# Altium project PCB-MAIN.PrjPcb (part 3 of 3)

## Sheet PCB-MAIN_07_BLE.SchDoc
size 594 x 420 mm
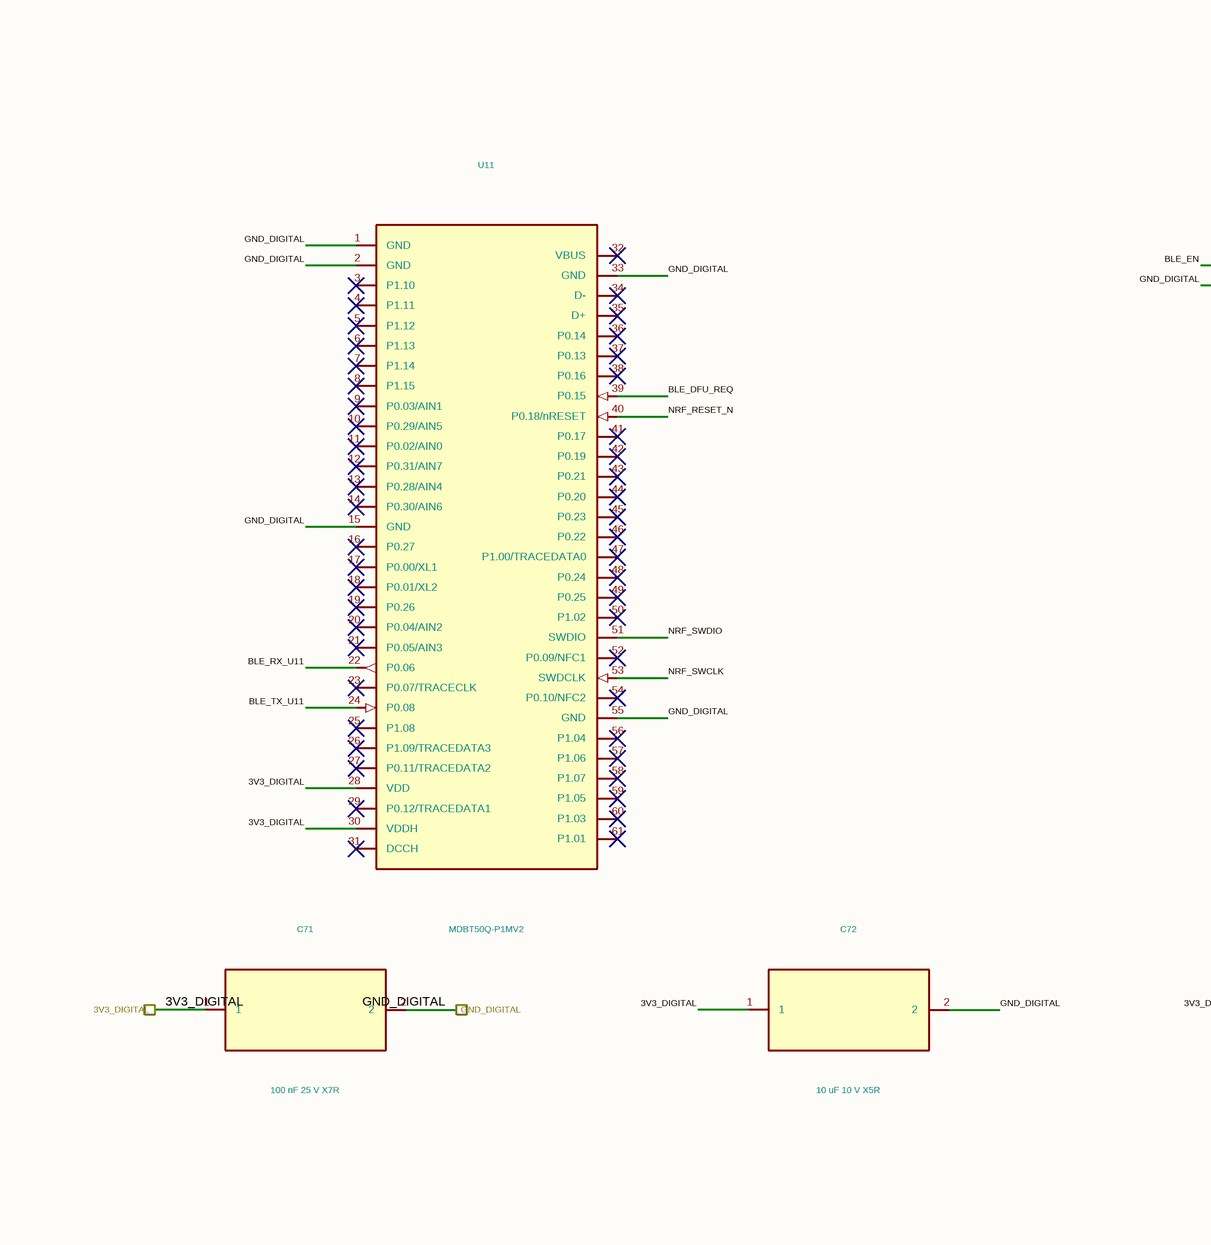
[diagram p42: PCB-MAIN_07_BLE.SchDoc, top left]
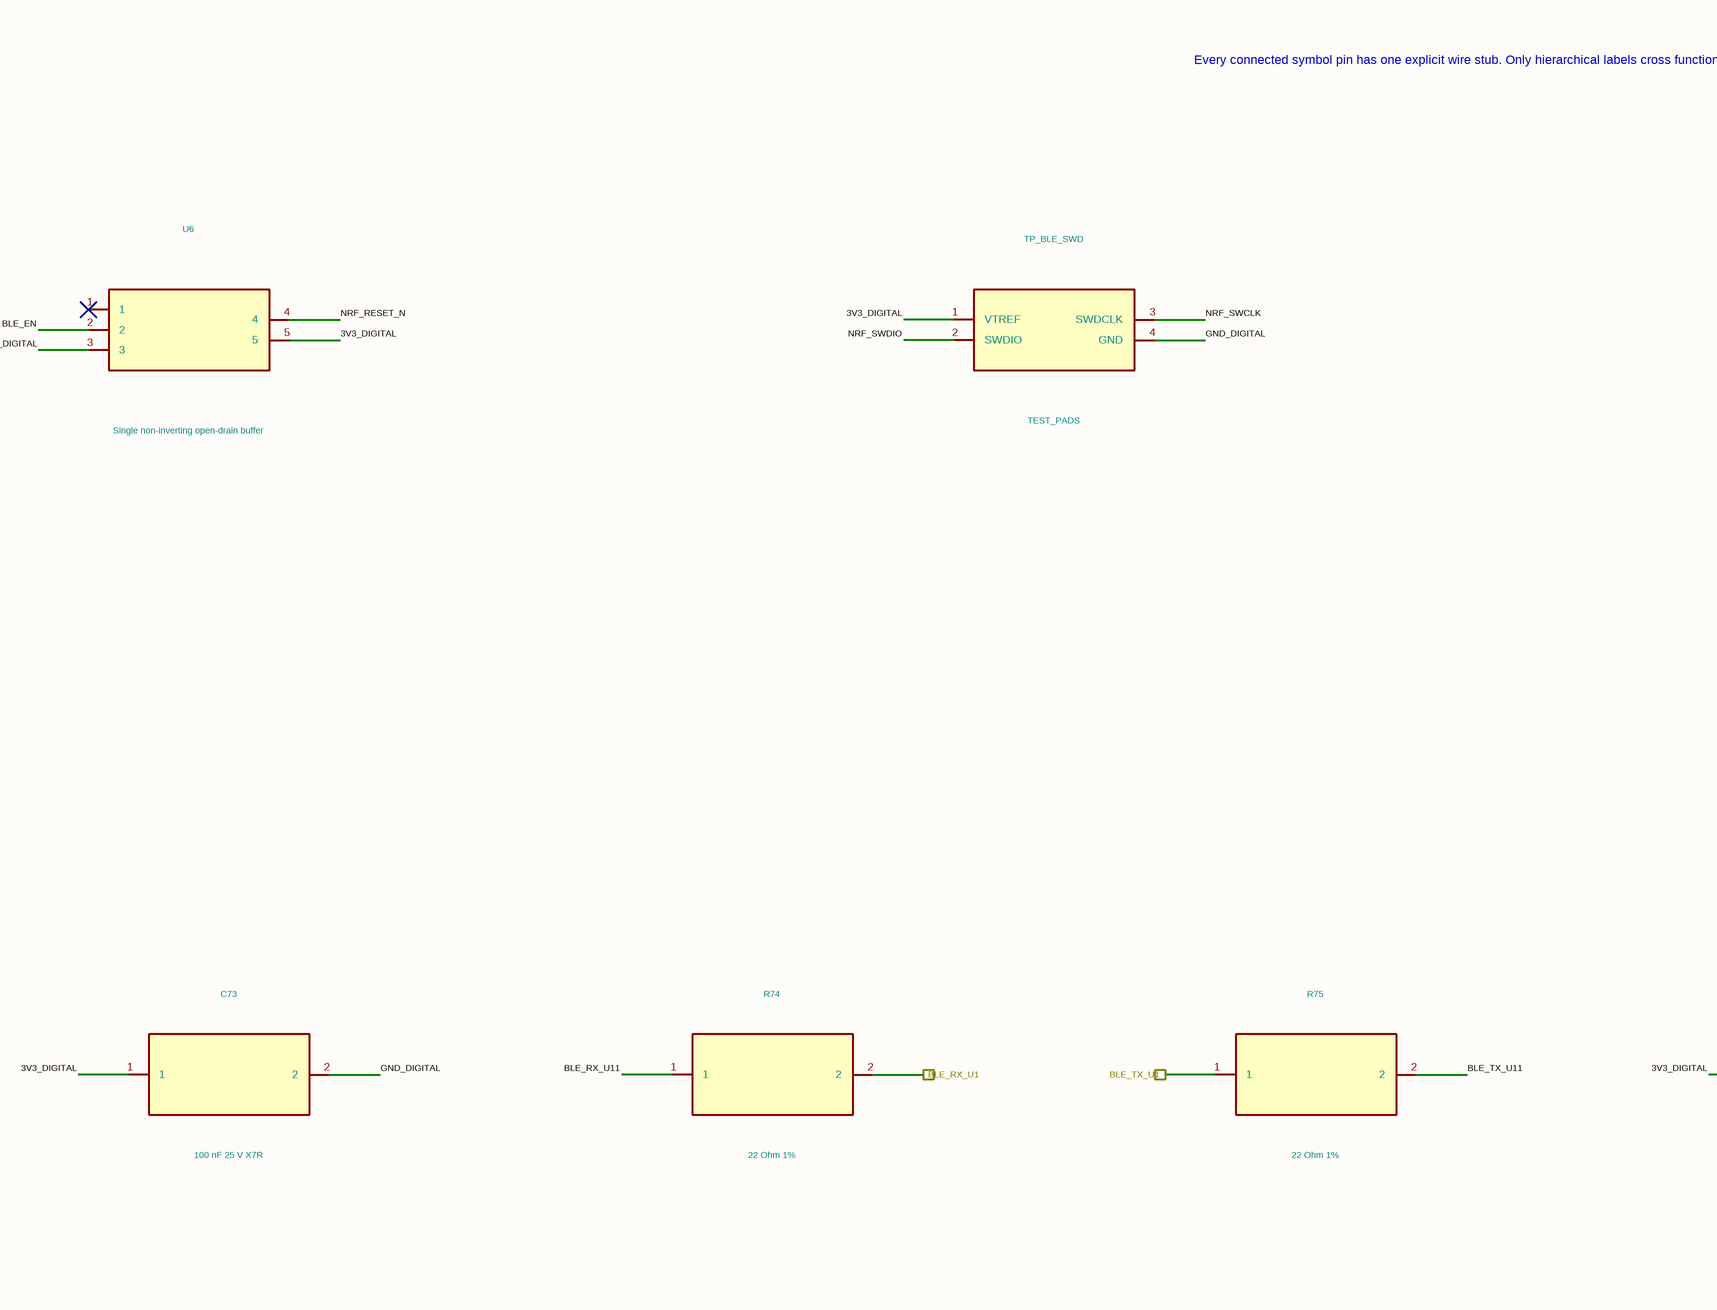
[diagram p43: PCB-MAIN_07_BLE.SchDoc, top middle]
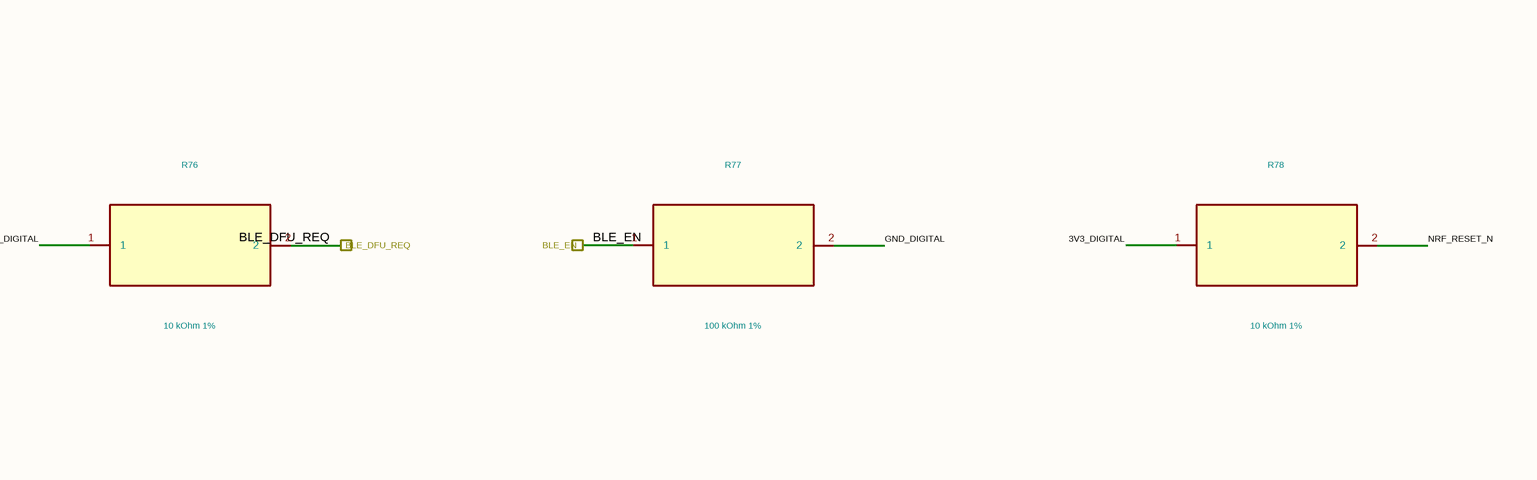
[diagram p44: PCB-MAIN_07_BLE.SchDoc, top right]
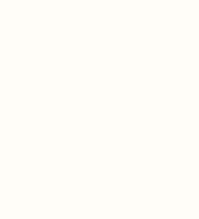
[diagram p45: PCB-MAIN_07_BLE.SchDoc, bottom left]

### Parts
C71  100 nF 25 V X7R  [C_0402_1005Metric]
C72  10 uF 10 V X5R  [C_0603_1608Metric]
C73  100 nF 25 V X7R  [C_0402_1005Metric]
R74  22 Ohm 1%  [R_0402_1005Metric]
R75  22 Ohm 1%  [R_0402_1005Metric]
R76  10 kOhm 1%  [R_0402_1005Metric]
R77  100 kOhm 1%  [R_0402_1005Metric]
R78  10 kOhm 1%  [R_0402_1005Metric]
TP_BLE_SWD  TEST_PADS
U6  Single non-inverting open-drain buffer
U11  MDBT50Q-P1MV2

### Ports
3V3_DIGITAL, BLE_DFU_REQ, BLE_EN, BLE_RX_U1, BLE_TX_U1, GND_DIGITAL

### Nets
3V3_DIGITAL: C71.1 C72.1 C73.1 R76.1 R78.1 TP_BLE_SWD.1(VTREF) U6.5 U11.28(VDD) U11.30(VDDH) ; port 3V3_DIGITAL
BLE_DFU_REQ: R76.2 U11.39(P0.15) ; port BLE_DFU_REQ
BLE_EN: R77.1 U6.2 ; port BLE_EN
BLE_RX_U1: R74.2 ; port BLE_RX_U1
BLE_RX_U11: R74.1 U11.22(P0.06)
BLE_TX_U1: R75.1 ; port BLE_TX_U1
BLE_TX_U11: R75.2 U11.24(P0.08)
GND_DIGITAL: C71.2 C72.2 C73.2 R77.2 TP_BLE_SWD.4(GND) U6.3 U11.1(GND) U11.2(GND) U11.15(GND) U11.33(GND) U11.55(GND) ; port GND_DIGITAL
NRF_RESET_N: R78.2 U6.4 U11.40(P0.18/nRESET)
NRF_SWCLK: TP_BLE_SWD.3(SWDCLK) U11.53(SWDCLK)
NRF_SWDIO: TP_BLE_SWD.2(SWDIO) U11.51(SWDIO)

Not connected (* = marked no-connect by the designer): U6 1*; U11 3(P1.10)* 4(P1.11)* 5(P1.12)* 6(P1.13)* 7(P1.14)* 8(P1.15)* 9(P0.03/AIN1)* 10(P0.29/AIN5)* 11(P0.02/AIN0)* 12(P0.31/AIN7)* 13(P0.28/AIN4)* 14(P0.30/AIN6)* 16(P0.27)* 17(P0.00/XL1)* 18(P0.01/XL2)* 19(P0.26)* 20(P0.04/AIN2)* 21(P0.05/AIN3)* 23(P0.07/TRACECLK)* 25(P1.08)* 26(P1.09/TRACEDATA3)* 27(P0.11/TRACEDATA2)* 29(P0.12/TRACEDATA1)* 31(DCCH)* 32(VBUS)* 34(D-)* 35(D+)* 36(P0.14)* 37(P0.13)* 38(P0.16)* 41(P0.17)* 42(P0.19)* 43(P0.21)* 44(P0.20)* 45(P0.23)* 46(P0.22)* 47(P1.00/TRACEDATA0)* 48(P0.24)* 49(P0.25)* 50(P1.02)* 52(P0.09/NFC1)* 54(P0.10/NFC2)* 56(P1.04)* 57(P1.06)* 58(P1.07)* 59(P1.05)* 60(P1.03)* 61(P1.01)*

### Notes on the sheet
- Every connected symbol pin has one explicit wire stub. Only hierarchical labels cross functional-sheet boundaries.

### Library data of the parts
C71 = C71_GRM155R71E104KE14D: Manufacturer: Murata; Population: FITTED; Authority: Raytac_MDBT50Q_Spec_Version_L
C72 = C72_GRM188R61A106KE69D: Manufacturer: Murata; Population: FITTED; Authority: Raytac_MDBT50Q_Spec_Version_L
C73 = C73_GRM155R71E104KE14D: Manufacturer: Murata; Population: FITTED; Authority: TI_SN74LVC1G07_datasheet
R74 = R74_ERJ-2RKF22R0X: Manufacturer: Panasonic; Population: FITTED; Authority: Raytac_MDBT50Q_Spec_Version_L
R75 = R75_ERJ-2RKF22R0X: Manufacturer: Panasonic; Population: FITTED; Authority: Raytac_MDBT50Q_Spec_Version_L
R76 = R76_ERJ-2RKF1002X: Manufacturer: Panasonic; Population: FITTED; Authority: Raytac_MDBT50Q_Spec_Version_L
R77 = R77_ERJ-2RKF1003X: Manufacturer: Panasonic; Population: FITTED; Authority: TI_SN74LVC1G07_datasheet
R78 = R78_ERJ-2RKF1002X: Manufacturer: Panasonic; Population: FITTED; Authority: TI_SN74LVC1G07_datasheet
TP_BLE_SWD = TP_BLE_SWD_TEST_PADS: Manufacturer: CONTROLLED_AUTHORITY; Population: FITTED; Authority: PCB_MAIN_BLE_PIN_AUTHORITY_REV_A.csv
U6 = U6_SN74LVC1G07DBVR: Manufacturer: Texas Instruments; Population: FITTED; Authority: TI_SN74LVC1G07_datasheet
U11 = U11_MDBT50Q-P1MV2: Manufacturer: Raytac; Population: FITTED; Authority: PCB_MAIN_BLE_PIN_AUTHORITY_REV_A.csv

## Sheet PCB-MAIN_08_STORAGE_SENSORS.SchDoc
size 594 x 420 mm
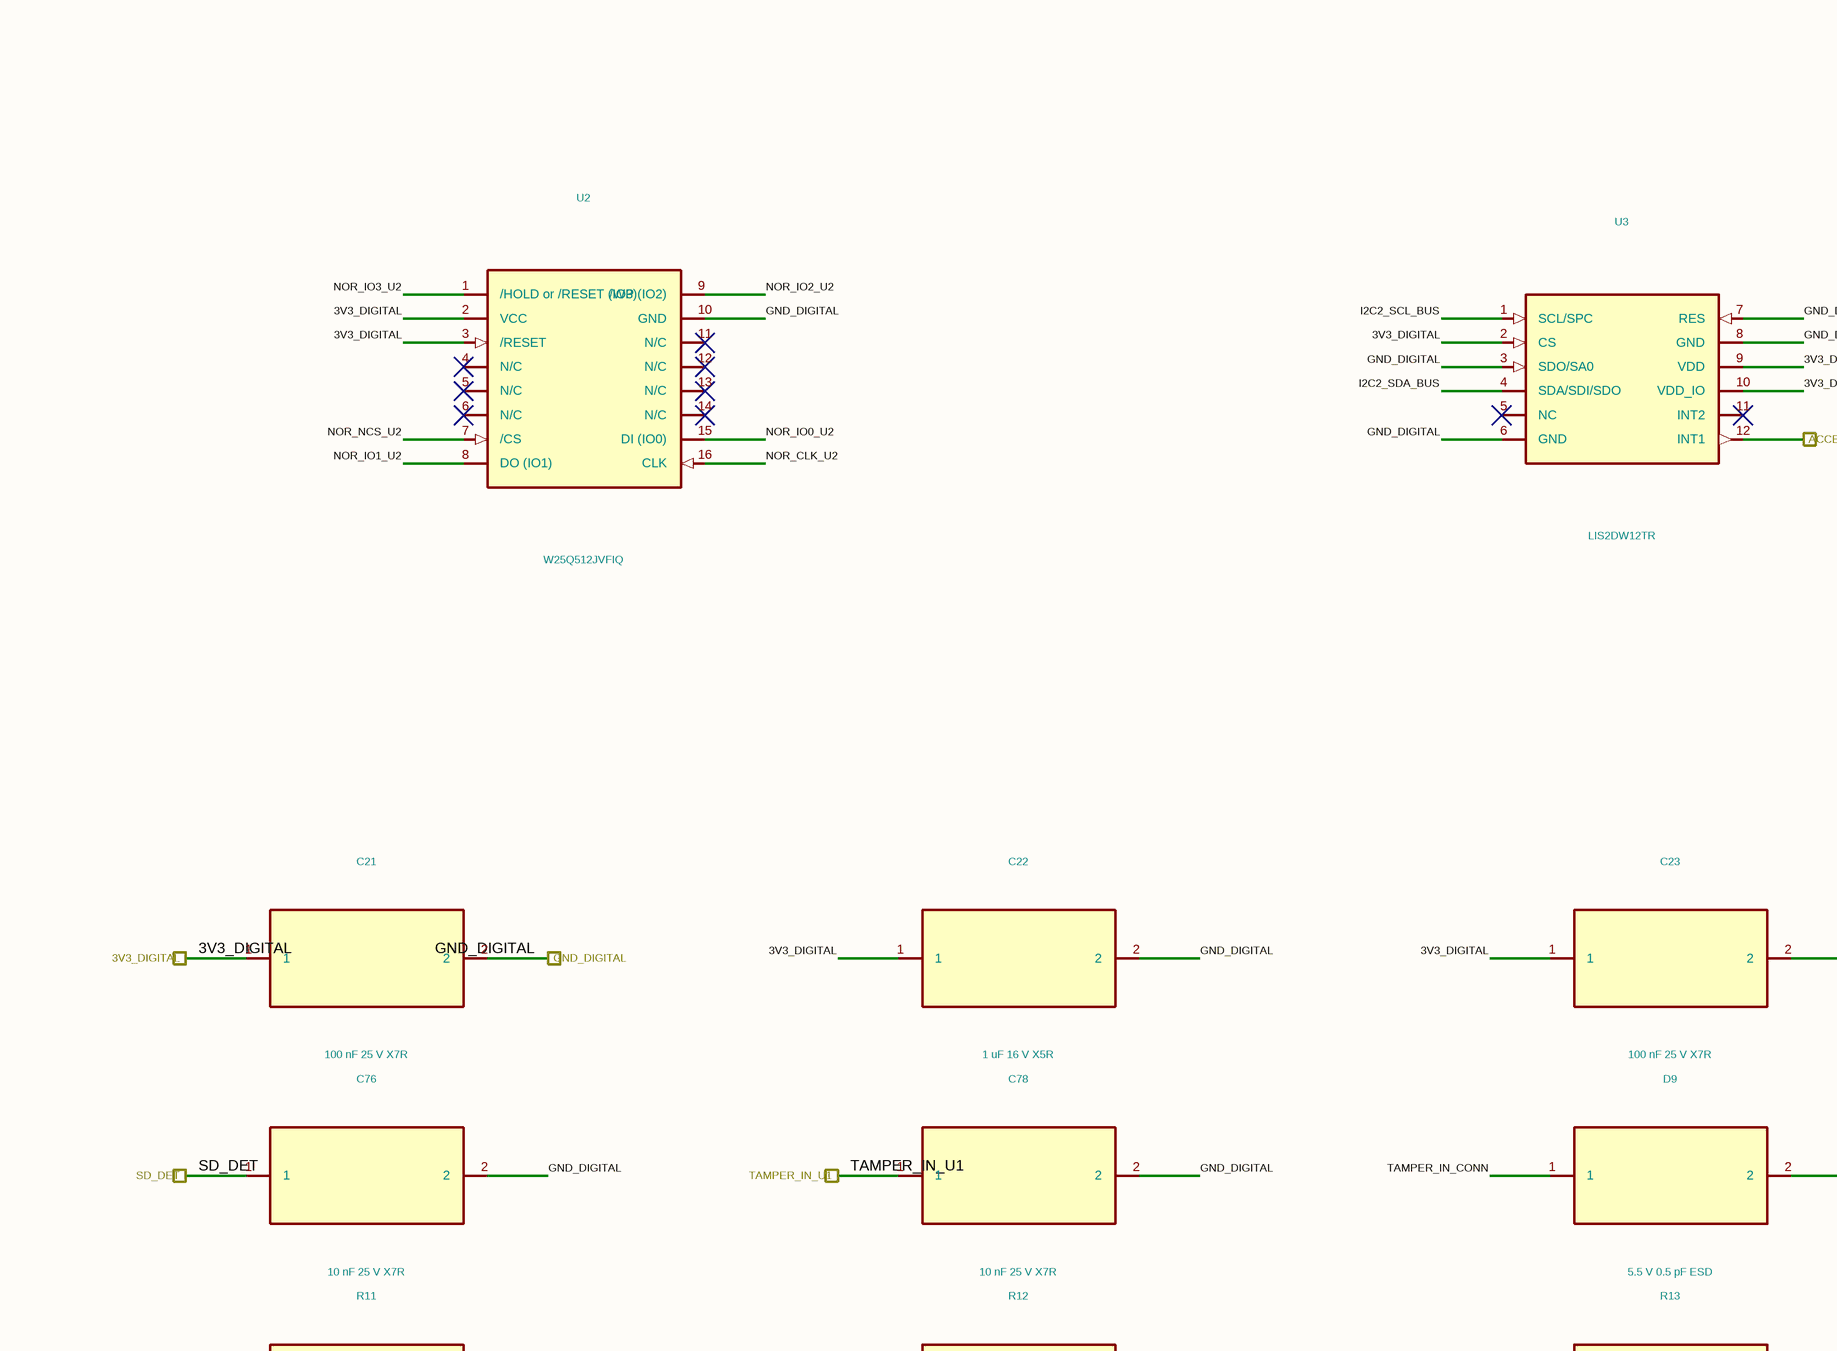
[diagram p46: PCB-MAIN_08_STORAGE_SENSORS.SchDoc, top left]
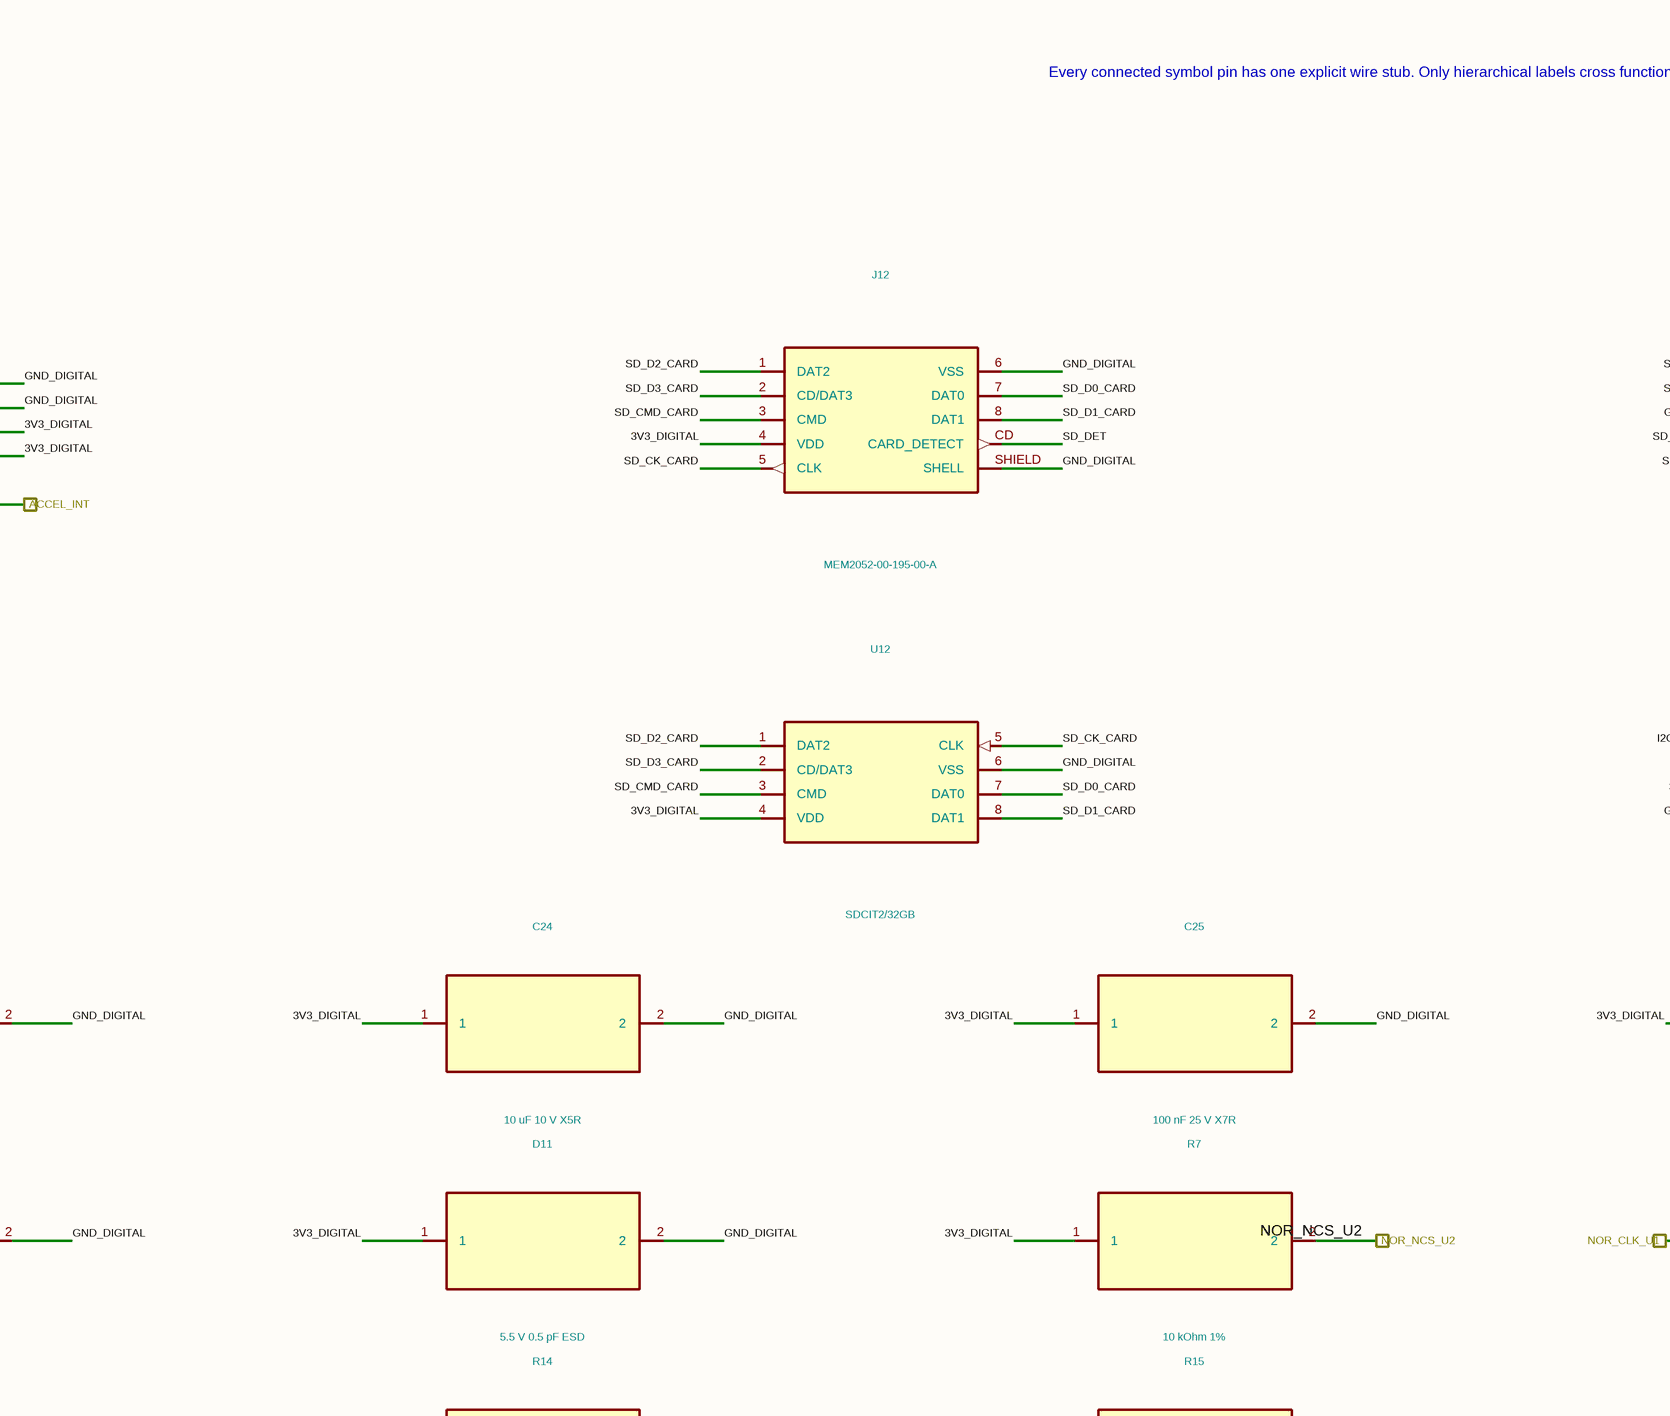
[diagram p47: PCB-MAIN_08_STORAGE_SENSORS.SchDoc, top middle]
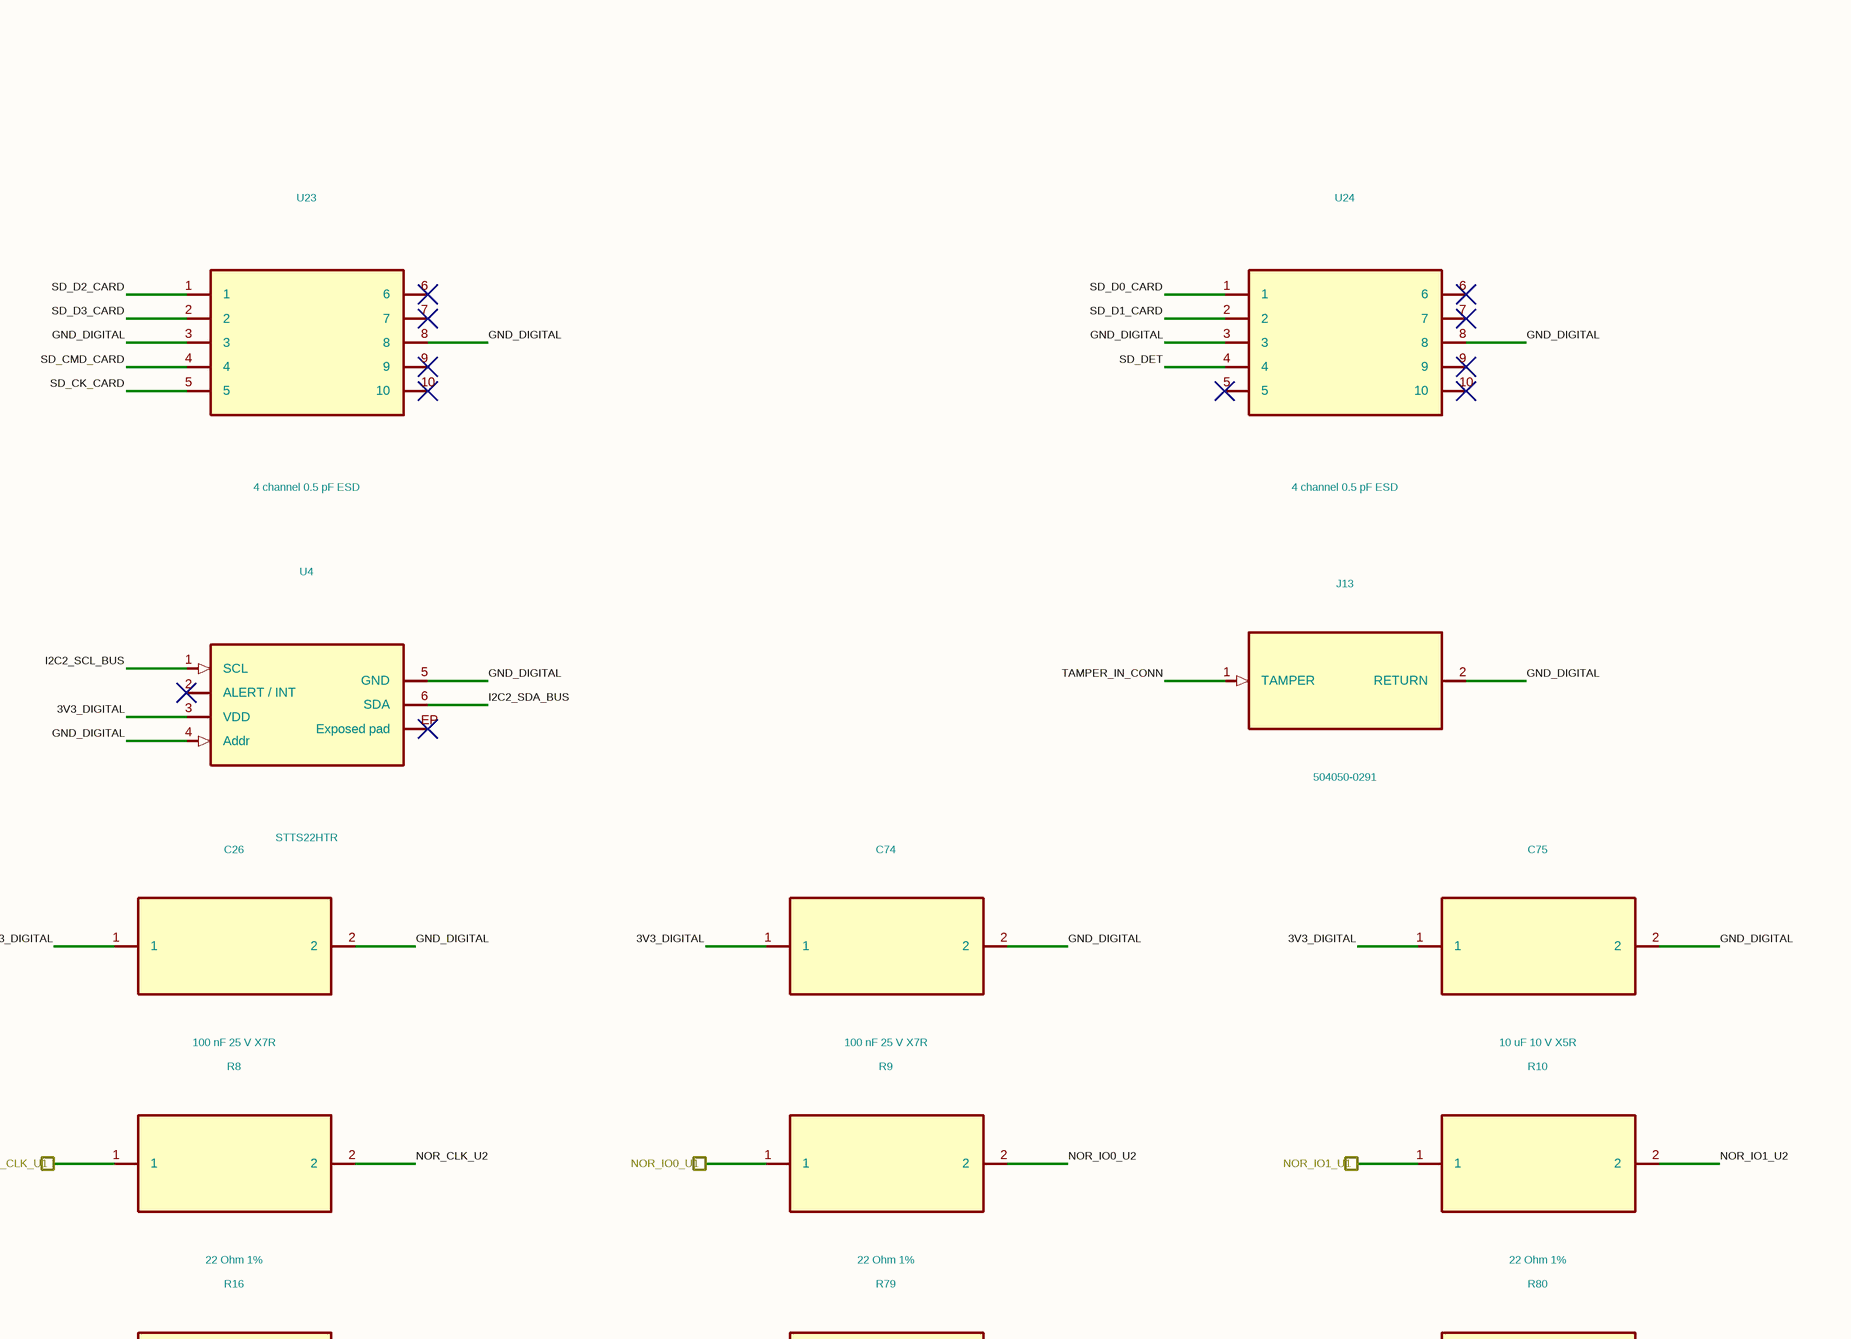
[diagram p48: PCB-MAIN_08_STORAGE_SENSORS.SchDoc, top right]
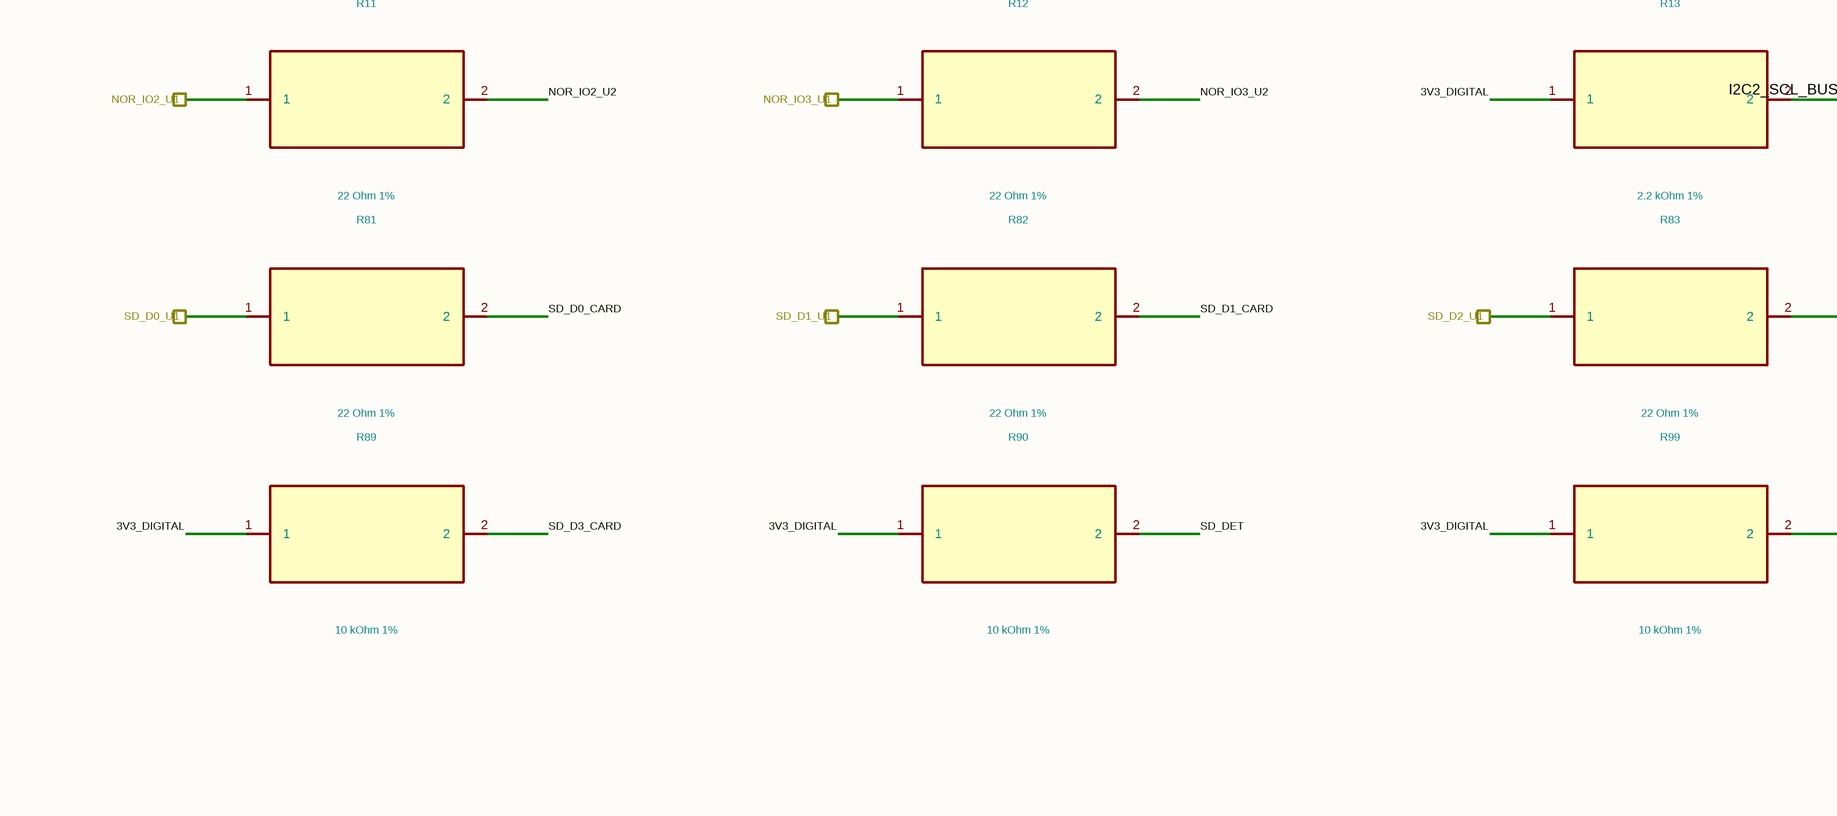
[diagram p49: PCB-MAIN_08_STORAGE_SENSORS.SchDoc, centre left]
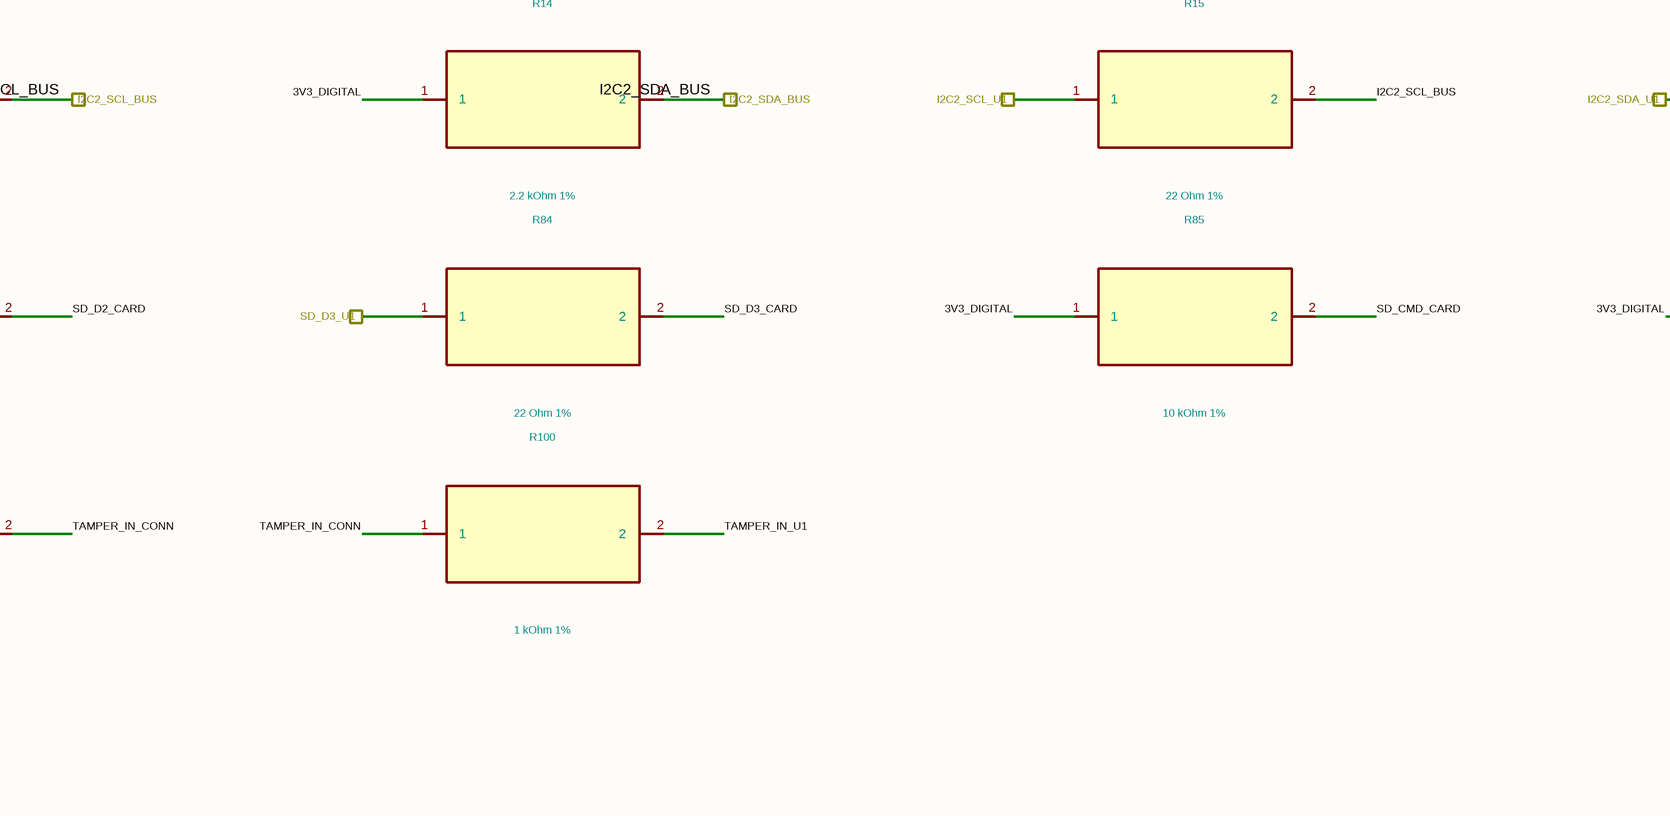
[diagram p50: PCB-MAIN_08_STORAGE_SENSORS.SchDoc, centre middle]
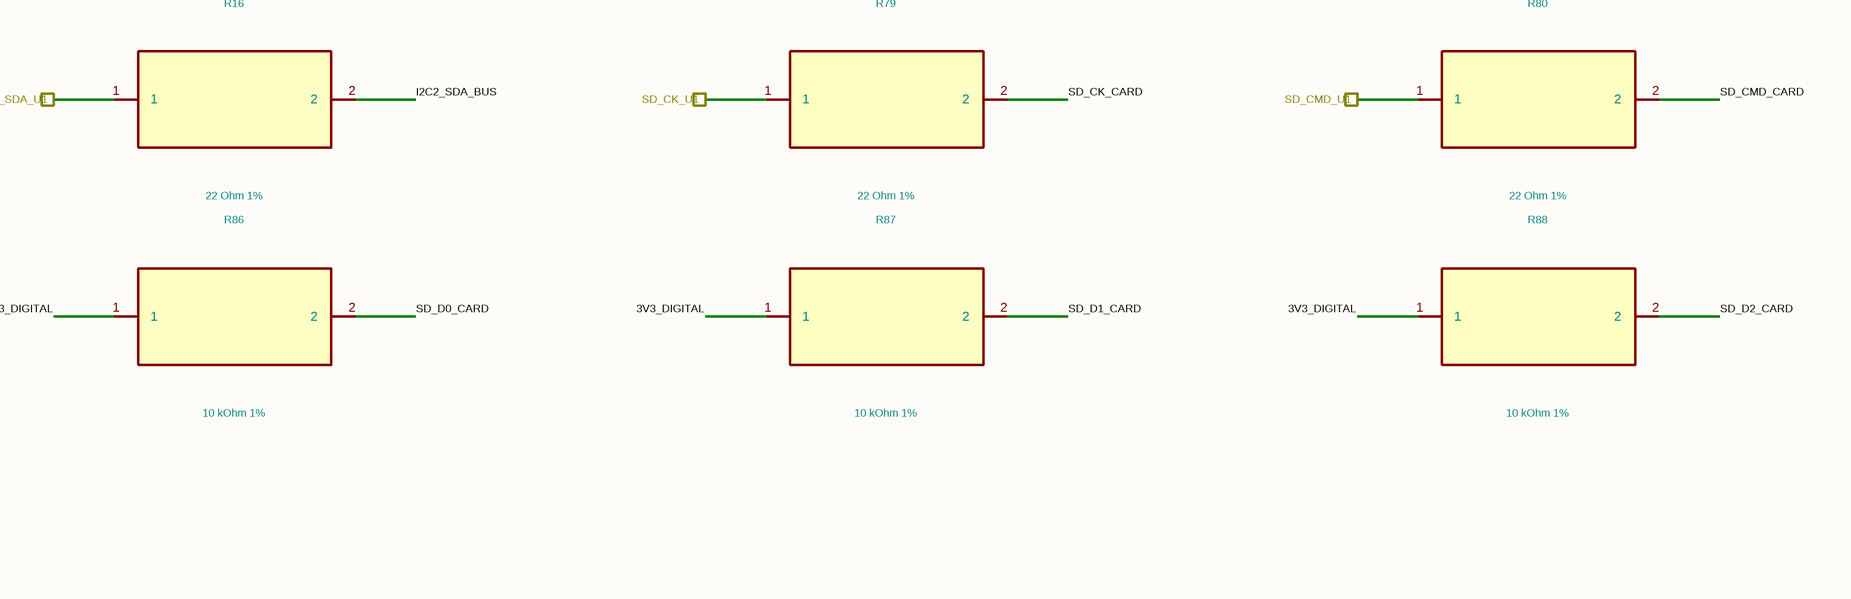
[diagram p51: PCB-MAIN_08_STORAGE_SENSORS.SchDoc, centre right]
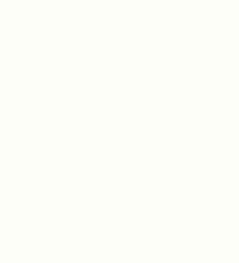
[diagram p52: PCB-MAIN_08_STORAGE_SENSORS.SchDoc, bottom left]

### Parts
C21  100 nF 25 V X7R  [C_0402_1005Metric]
C22  1 uF 16 V X5R  [C_0402_1005Metric]
C23  100 nF 25 V X7R  [C_0402_1005Metric]
C24  10 uF 10 V X5R  [C_0603_1608Metric]
C25  100 nF 25 V X7R  [C_0402_1005Metric]
C26  100 nF 25 V X7R  [C_0402_1005Metric]
C74  100 nF 25 V X7R  [C_0402_1005Metric]
C75  10 uF 10 V X5R  [C_0603_1608Metric]
C76  10 nF 25 V X7R  [C_0402_1005Metric]
C78  10 nF 25 V X7R  [C_0402_1005Metric]
D9  5.5 V 0.5 pF ESD
D11  5.5 V 0.5 pF ESD
J12  MEM2052-00-195-00-A
J13  504050-0291
R7  10 kOhm 1%  [R_0402_1005Metric]
R8  22 Ohm 1%  [R_0402_1005Metric]
R9  22 Ohm 1%  [R_0402_1005Metric]
R10  22 Ohm 1%  [R_0402_1005Metric]
R11  22 Ohm 1%  [R_0402_1005Metric]
R12  22 Ohm 1%  [R_0402_1005Metric]
R13  2.2 kOhm 1%  [R_0402_1005Metric]
R14  2.2 kOhm 1%  [R_0402_1005Metric]
R15  22 Ohm 1%  [R_0402_1005Metric]
R16  22 Ohm 1%  [R_0402_1005Metric]
R79  22 Ohm 1%  [R_0402_1005Metric]
R80  22 Ohm 1%  [R_0402_1005Metric]
R81  22 Ohm 1%  [R_0402_1005Metric]
R82  22 Ohm 1%  [R_0402_1005Metric]
R83  22 Ohm 1%  [R_0402_1005Metric]
R84  22 Ohm 1%  [R_0402_1005Metric]
R85  10 kOhm 1%  [R_0402_1005Metric]
R86  10 kOhm 1%  [R_0402_1005Metric]
R87  10 kOhm 1%  [R_0402_1005Metric]
R88  10 kOhm 1%  [R_0402_1005Metric]
R89  10 kOhm 1%  [R_0402_1005Metric]
R90  10 kOhm 1%  [R_0402_1005Metric]
R99  10 kOhm 1%  [R_0402_1005Metric]
R100  1 kOhm 1%  [R_0402_1005Metric]
U2  W25Q512JVFIQ
U3  LIS2DW12TR
U4  STTS22HTR
U12  SDCIT2/32GB
U23  4 channel 0.5 pF ESD
U24  4 channel 0.5 pF ESD

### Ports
3V3_DIGITAL, ACCEL_INT, GND_DIGITAL, I2C2_SCL_BUS, I2C2_SCL_U1, I2C2_SDA_BUS, I2C2_SDA_U1, NOR_CLK_U1, NOR_IO0_U1, NOR_IO1_U1, NOR_IO2_U1, NOR_IO3_U1, NOR_NCS_U2, SD_CK_U1, SD_CMD_U1, SD_D0_U1, SD_D1_U1, SD_D2_U1, SD_D3_U1, SD_DET, TAMPER_IN_U1

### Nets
3V3_DIGITAL: C21.1 C22.1 C23.1 C24.1 C25.1 C26.1 C74.1 C75.1 D11.1 J12.4(VDD) R7.1 R13.1 R14.1 R85.1 R86.1 R87.1 R88.1 R89.1 R90.1 R99.1 U2.2(VCC) U2.3(/RESET) U3.2(CS) U3.9(VDD) U3.10(VDD_IO) U4.3(VDD) U12.4(VDD) ; port 3V3_DIGITAL
ACCEL_INT: U3.12(INT1) ; port ACCEL_INT
GND_DIGITAL: C21.2 C22.2 C23.2 C24.2 C25.2 C26.2 C74.2 C75.2 C76.2 C78.2 D9.2 D11.2 J12.6(VSS) J12.SHIELD(SHELL) J13.2(RETURN) U2.10(GND) U3.3(SDO/SA0) U3.6(GND) U3.7(RES) U3.8(GND) U4.4(Addr) U4.5(GND) U12.6(VSS) U23.3 U23.8 U24.3 U24.8 ; port GND_DIGITAL
I2C2_SCL_BUS: R13.2 R15.2 U3.1(SCL/SPC) U4.1(SCL) ; port I2C2_SCL_BUS
I2C2_SCL_U1: R15.1 ; port I2C2_SCL_U1
I2C2_SDA_BUS: R14.2 R16.2 U3.4(SDA/SDI/SDO) U4.6(SDA) ; port I2C2_SDA_BUS
I2C2_SDA_U1: R16.1 ; port I2C2_SDA_U1
NOR_CLK_U1: R8.1 ; port NOR_CLK_U1
NOR_CLK_U2: R8.2 U2.16(CLK)
NOR_IO0_U1: R9.1 ; port NOR_IO0_U1
NOR_IO0_U2: R9.2 U2.15(DI_(IO0))
NOR_IO1_U1: R10.1 ; port NOR_IO1_U1
NOR_IO1_U2: R10.2 U2.8(DO_(IO1))
NOR_IO2_U1: R11.1 ; port NOR_IO2_U1
NOR_IO2_U2: R11.2 U2.9(/WP_(IO2))
NOR_IO3_U1: R12.1 ; port NOR_IO3_U1
NOR_IO3_U2: R12.2 U2.1(/HOLD_or_/RESET_(IO3))
NOR_NCS_U2: R7.2 U2.7(/CS) ; port NOR_NCS_U2
SD_CK_CARD: J12.5(CLK) R79.2 U12.5(CLK) U23.5
SD_CK_U1: R79.1 ; port SD_CK_U1
SD_CMD_CARD: J12.3(CMD) R80.2 R85.2 U12.3(CMD) U23.4
SD_CMD_U1: R80.1 ; port SD_CMD_U1
SD_D0_CARD: J12.7(DAT0) R81.2 R86.2 U12.7(DAT0) U24.1
SD_D0_U1: R81.1 ; port SD_D0_U1
SD_D1_CARD: J12.8(DAT1) R82.2 R87.2 U12.8(DAT1) U24.2
SD_D1_U1: R82.1 ; port SD_D1_U1
SD_D2_CARD: J12.1(DAT2) R83.2 R88.2 U12.1(DAT2) U23.1
SD_D2_U1: R83.1 ; port SD_D2_U1
SD_D3_CARD: J12.2(CD/DAT3) R84.2 R89.2 U12.2(CD/DAT3) U23.2
SD_D3_U1: R84.1 ; port SD_D3_U1
SD_DET: C76.1 J12.CD(CARD_DETECT) R90.2 U24.4 ; port SD_DET
TAMPER_IN_CONN: D9.1 J13.1(TAMPER) R99.2 R100.1
TAMPER_IN_U1: C78.1 R100.2 ; port TAMPER_IN_U1

Not connected (* = marked no-connect by the designer): U2 4(N/C)* 5(N/C)* 6(N/C)* 11(N/C)* 12(N/C)* 13(N/C)* 14(N/C)*; U3 5(NC)* 11(INT2)*; U4 2(ALERT_/_INT)* EP(Exposed_pad)*; U23 6* 7* 9* 10*; U24 5* 6* 7* 9* 10*

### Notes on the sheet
- Every connected symbol pin has one explicit wire stub. Only hierarchical labels cross functional-sheet boundaries.

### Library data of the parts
C21 = C21_GRM155R71E104KE14D: Manufacturer: Murata; Population: FITTED; Authority: Winbond_W25Q512JV_RevB
C22 = C22_GRM155R61C105KA12D: Manufacturer: Murata; Population: FITTED; Authority: Winbond_W25Q512JV_RevB
C23 = C23_GRM155R71E104KE14D: Manufacturer: Murata; Population: FITTED; Authority: ST_LIS2DW12_DS11811_Rev9
C24 = C24_GRM188R61A106KE69D: Manufacturer: Murata; Population: FITTED; Authority: ST_LIS2DW12_DS11811_Rev9
C25 = C25_GRM155R71E104KE14D: Manufacturer: Murata; Population: FITTED; Authority: ST_LIS2DW12_DS11811_Rev9
C26 = C26_GRM155R71E104KE14D: Manufacturer: Murata; Population: FITTED; Authority: ST_STTS22H_DS12606_Rev8
C74 = C74_GRM155R71E104KE14D: Manufacturer: Murata; Population: FITTED; Authority: SD_Association_microSD
C75 = C75_GRM188R61A106KE69D: Manufacturer: Murata; Population: FITTED; Authority: SD_Association_microSD
C76 = C76_GRM155R71E103KA01D: Manufacturer: Murata; Population: FITTED; Authority: GCT_MEM2052_official_product_data
C78 = C78_GRM155R71E103KA01D: Manufacturer: Murata; Population: FITTED; Authority: PROJECT_MAIN_AUTH_010
D9 = D9_TPD1E05U06DYAR: Manufacturer: Texas Instruments; Population: FITTED; Authority: TI_TPDxE05U06_RevO
D11 = D11_TPD1E05U06DYAR: Manufacturer: Texas Instruments; Population: FITTED; Authority: TI_TPDxE05U06_RevO
J12 = J12_MEM2052-00-195-00-A: Manufacturer: CONTROLLED_AUTHORITY; Population: FITTED; Authority: PCB_MAIN_CONNECTOR_FIXTURE_PIN_AUTHORITY_REV_A.csv
J13 = J13_504050-0291: Manufacturer: CONTROLLED_AUTHORITY; Population: FITTED; Authority: PCB_MAIN_CONNECTOR_FIXTURE_PIN_AUTHORITY_REV_A.csv
R7 = R7_ERJ-2RKF1002X: Manufacturer: Panasonic; Population: FITTED; Authority: Winbond_W25Q512JV_RevB
R8 = R8_ERJ-2RKF22R0X: Manufacturer: Panasonic; Population: FITTED; Authority: PROJECT_MAIN_AUTH_010
R9 = R9_ERJ-2RKF22R0X: Manufacturer: Panasonic; Population: FITTED; Authority: PROJECT_MAIN_AUTH_010
R10 = R10_ERJ-2RKF22R0X: Manufacturer: Panasonic; Population: FITTED; Authority: PROJECT_MAIN_AUTH_010
R11 = R11_ERJ-2RKF22R0X: Manufacturer: Panasonic; Population: FITTED; Authority: PROJECT_MAIN_AUTH_010
R12 = R12_ERJ-2RKF22R0X: Manufacturer: Panasonic; Population: FITTED; Authority: PROJECT_MAIN_AUTH_010
R13 = R13_ERJ-2RKF2201X: Manufacturer: Panasonic; Population: FITTED; Authority: I2C_UM10204
R14 = R14_ERJ-2RKF2201X: Manufacturer: Panasonic; Population: FITTED; Authority: I2C_UM10204
R15 = R15_ERJ-2RKF22R0X: Manufacturer: Panasonic; Population: FITTED; Authority: PROJECT_MAIN_AUTH_010
R16 = R16_ERJ-2RKF22R0X: Manufacturer: Panasonic; Population: FITTED; Authority: PROJECT_MAIN_AUTH_010
R79 = R79_ERJ-2RKF22R0X: Manufacturer: Panasonic; Population: FITTED; Authority: SD_Association_microSD
R80 = R80_ERJ-2RKF22R0X: Manufacturer: Panasonic; Population: FITTED; Authority: SD_Association_microSD
R81 = R81_ERJ-2RKF22R0X: Manufacturer: Panasonic; Population: FITTED; Authority: SD_Association_microSD
R82 = R82_ERJ-2RKF22R0X: Manufacturer: Panasonic; Population: FITTED; Authority: SD_Association_microSD
R83 = R83_ERJ-2RKF22R0X: Manufacturer: Panasonic; Population: FITTED; Authority: SD_Association_microSD
R84 = R84_ERJ-2RKF22R0X: Manufacturer: Panasonic; Population: FITTED; Authority: SD_Association_microSD
R85 = R85_ERJ-2RKF1002X: Manufacturer: Panasonic; Population: FITTED; Authority: SD_Association_microSD
R86 = R86_ERJ-2RKF1002X: Manufacturer: Panasonic; Population: FITTED; Authority: SD_Association_microSD
R87 = R87_ERJ-2RKF1002X: Manufacturer: Panasonic; Population: FITTED; Authority: SD_Association_microSD
R88 = R88_ERJ-2RKF1002X: Manufacturer: Panasonic; Population: FITTED; Authority: SD_Association_microSD
R89 = R89_ERJ-2RKF1002X: Manufacturer: Panasonic; Population: FITTED; Authority: SD_Association_microSD
R90 = R90_ERJ-2RKF1002X: Manufacturer: Panasonic; Population: FITTED; Authority: GCT_MEM2052_official_product_data
R99 = R99_ERJ-2RKF1002X: Manufacturer: Panasonic; Population: FITTED; Authority: PROJECT_MAIN_AUTH_010
R100 = R100_ERJ-2RKF1001X: Manufacturer: Panasonic; Population: FITTED; Authority: PROJECT_MAIN_AUTH_010
U2 = U2_W25Q512JVFIQ: Manufacturer: Winbond; Population: FITTED; Authority: PCB_MAIN_STORAGE_SENSOR_PIN_AUTHORITY_REV_A.csv
U3 = U3_LIS2DW12TR: Manufacturer: STMicroelectronics; Population: FITTED; Authority: PCB_MAIN_STORAGE_SENSOR_PIN_AUTHORITY_REV_A.csv
U4 = U4_STTS22HTR: Manufacturer: STMicroelectronics; Population: FITTED; Authority: PCB_MAIN_STORAGE_SENSOR_PIN_AUTHORITY_REV_A.csv
U12 = U12_SDCIT2_32GB: Manufacturer: Kingston; Population: FITTED; Authority: PCB_MAIN_CONNECTOR_FIXTURE_PIN_AUTHORITY_REV_A.csv
U23 = U23_TPD4E05U06DQAR: Manufacturer: Texas Instruments; Population: FITTED; Authority: TI_TPDxE05U06_RevO
U24 = U24_TPD4E05U06DQAR: Manufacturer: Texas Instruments; Population: FITTED; Authority: TI_TPDxE05U06_RevO

## Sheet PCB-MAIN_09_CONNECTORS_TEST.SchDoc
size 594 x 420 mm
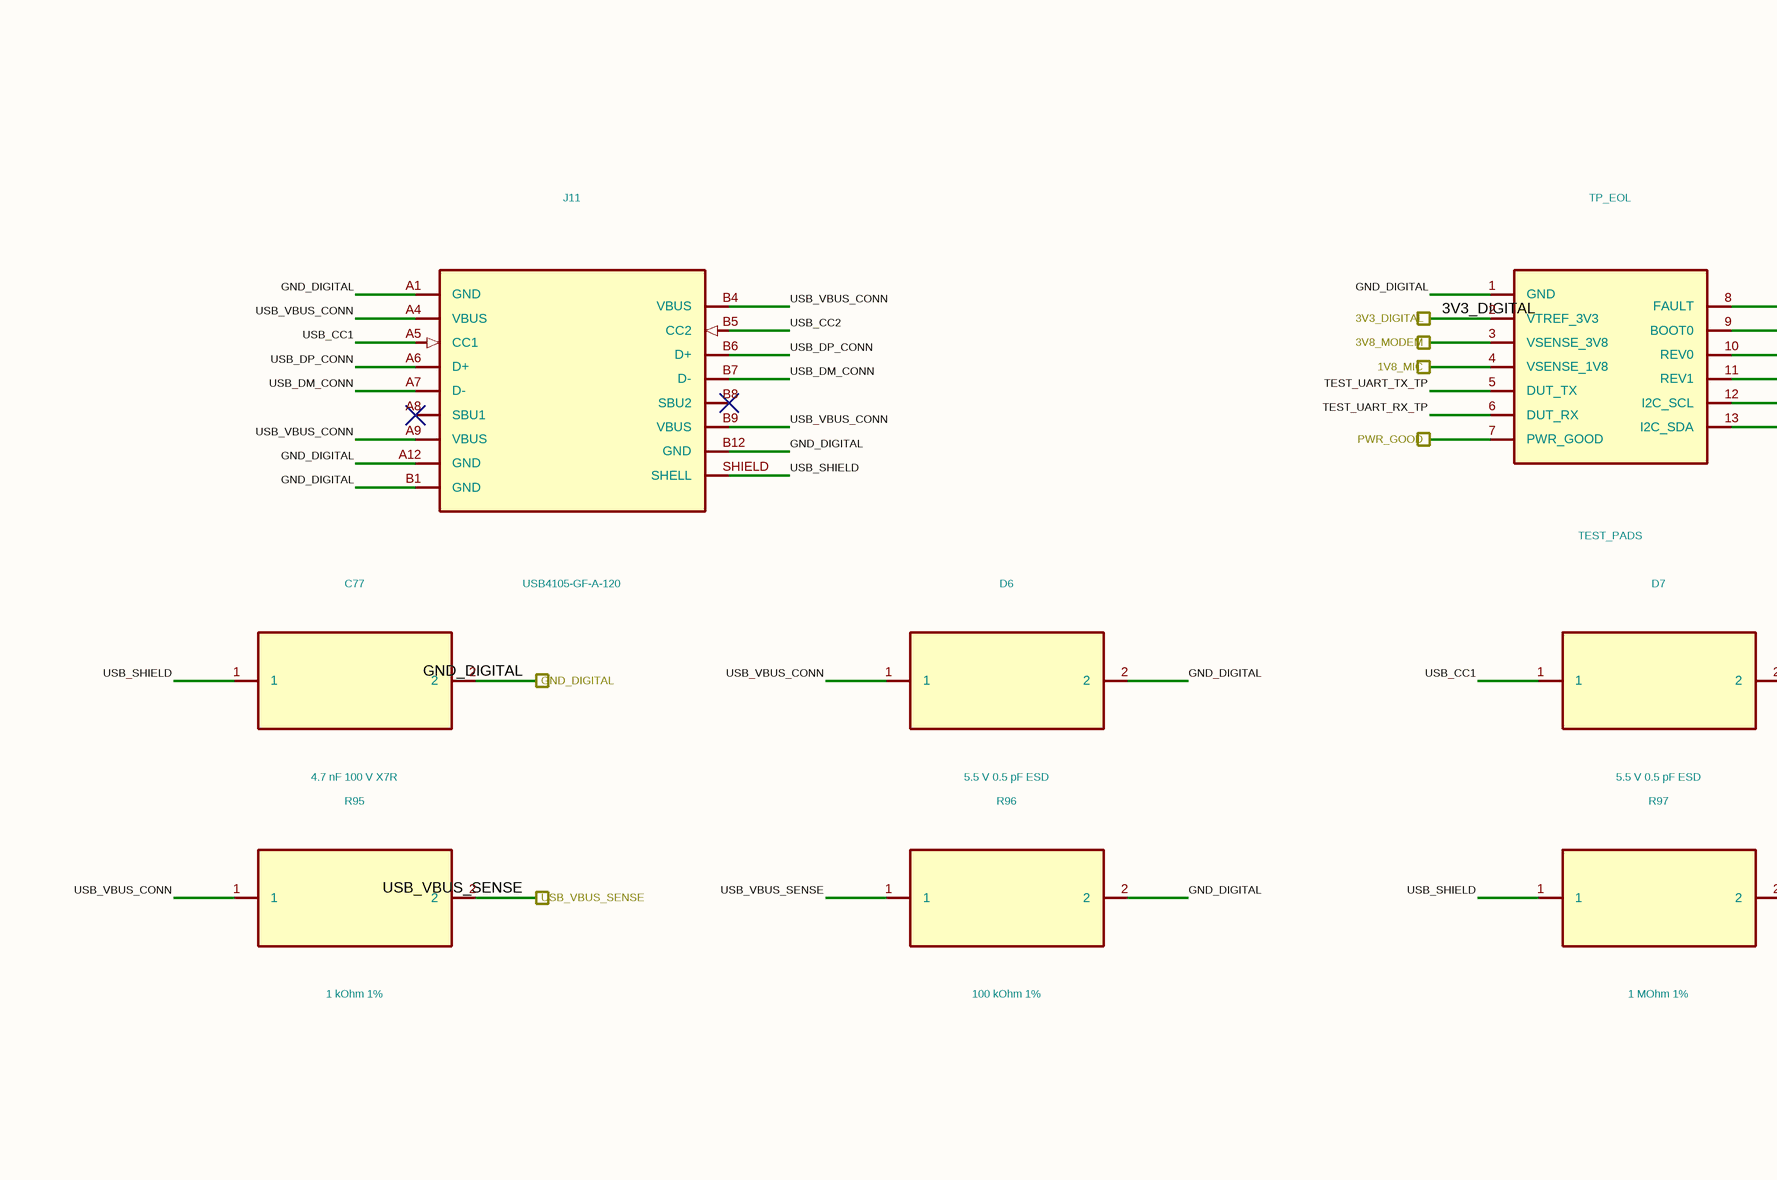
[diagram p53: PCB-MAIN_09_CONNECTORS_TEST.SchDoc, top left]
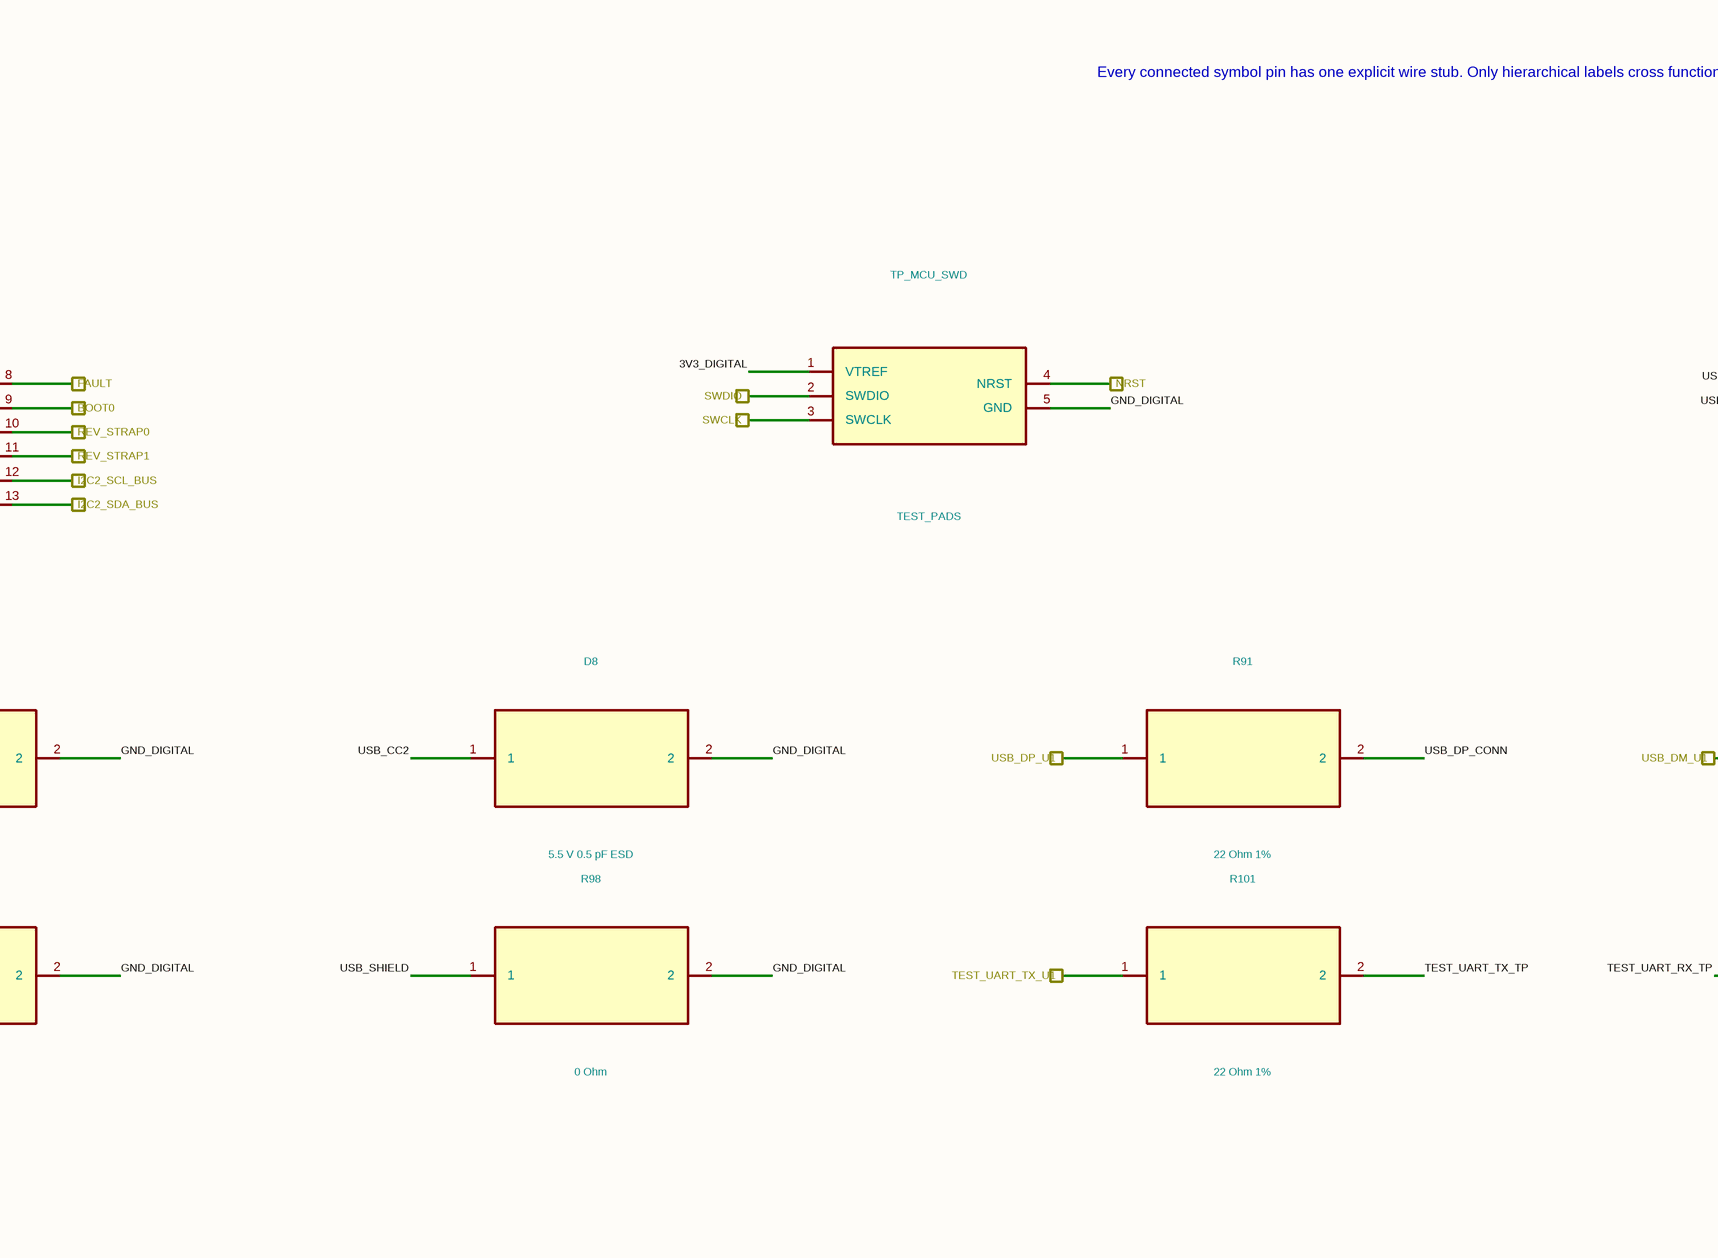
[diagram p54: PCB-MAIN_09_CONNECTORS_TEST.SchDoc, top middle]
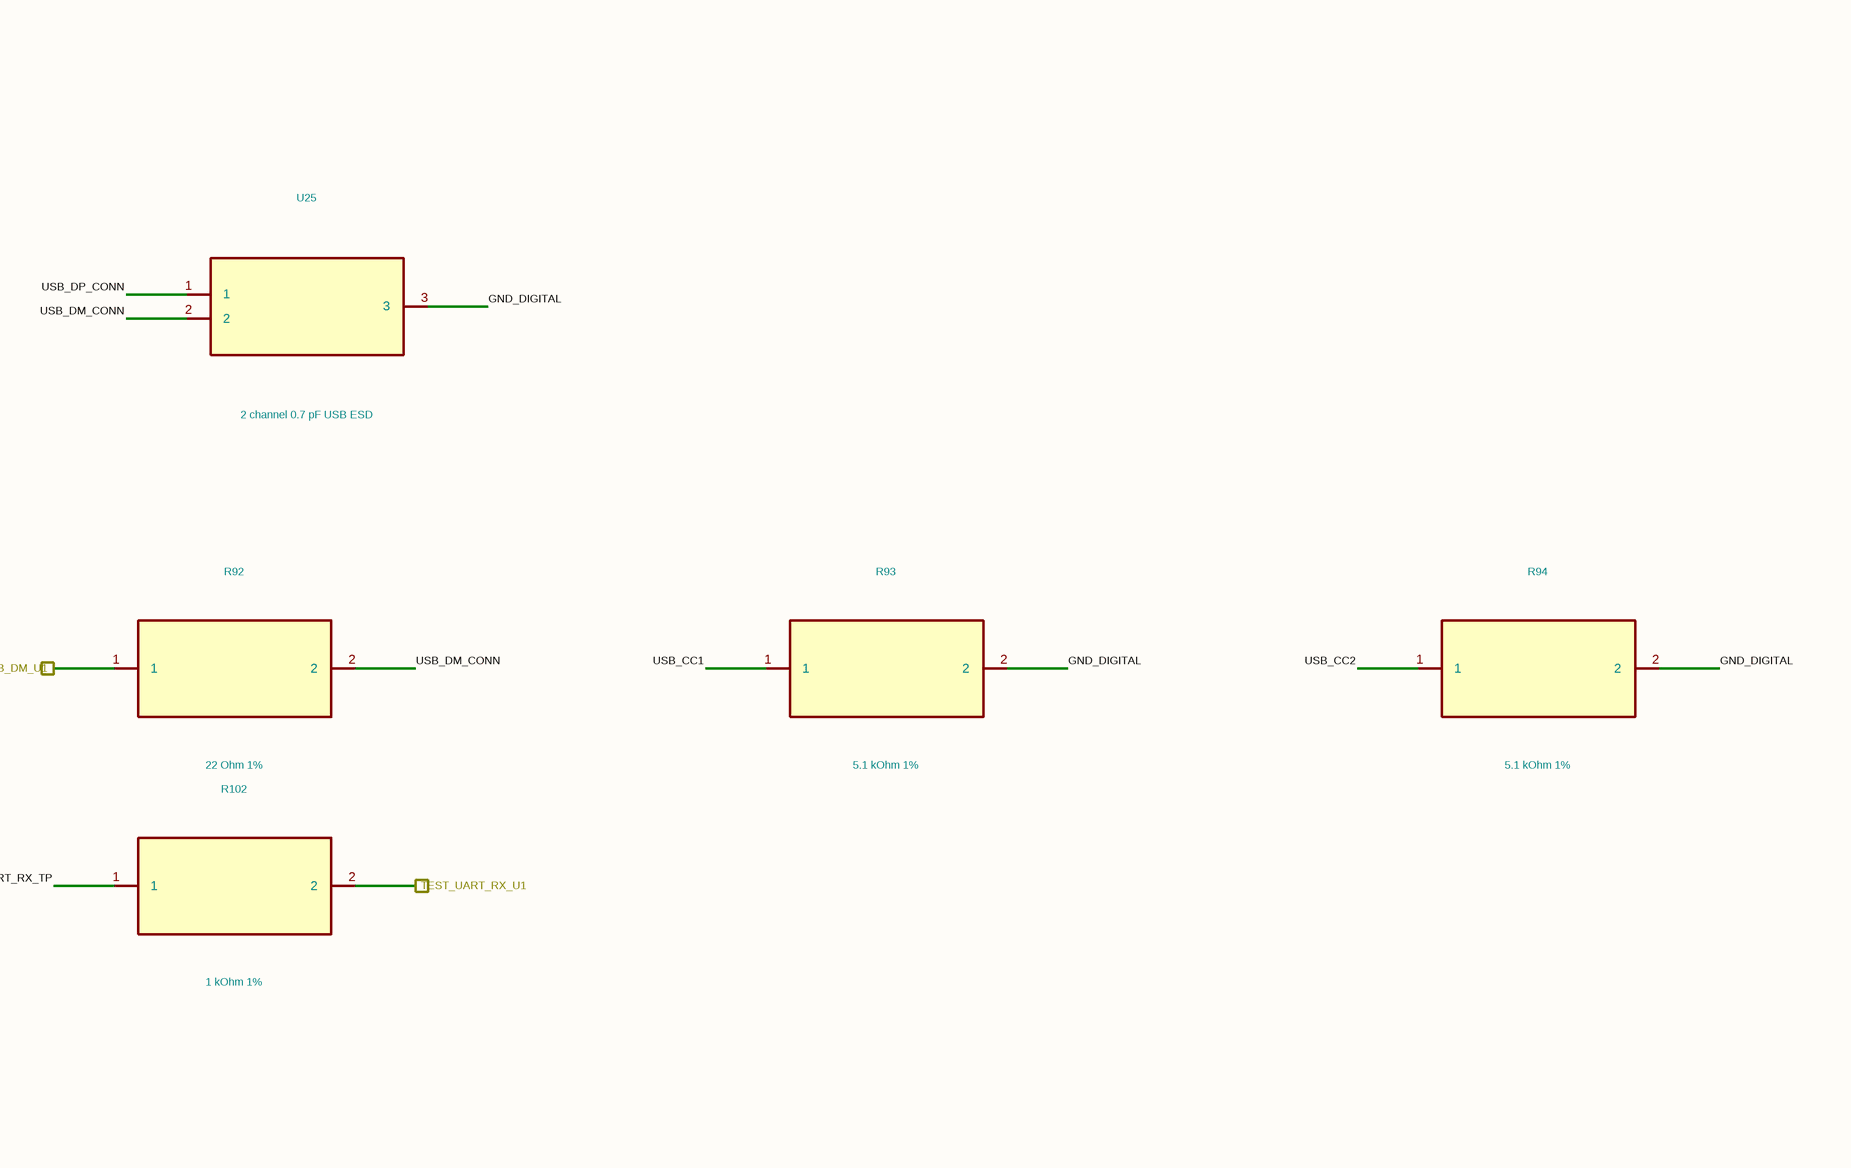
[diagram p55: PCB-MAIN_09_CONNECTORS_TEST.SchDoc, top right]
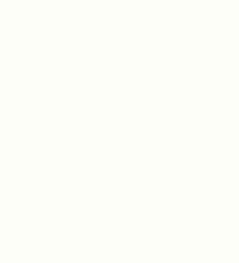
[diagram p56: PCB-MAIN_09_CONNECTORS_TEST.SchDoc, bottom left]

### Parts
C77  4.7 nF 100 V X7R  [C_0402_1005Metric]
D6  5.5 V 0.5 pF ESD
D7  5.5 V 0.5 pF ESD
D8  5.5 V 0.5 pF ESD
J11  USB4105-GF-A-120
R91  22 Ohm 1%  [R_0402_1005Metric]
R92  22 Ohm 1%  [R_0402_1005Metric]
R93  5.1 kOhm 1%  [R_0402_1005Metric]
R94  5.1 kOhm 1%  [R_0402_1005Metric]
R95  1 kOhm 1%  [R_0402_1005Metric]
R96  100 kOhm 1%  [R_0402_1005Metric]
R97  1 MOhm 1%  [R_0402_1005Metric]
R98  0 Ohm  [R_0402_1005Metric]
R101  22 Ohm 1%  [R_0402_1005Metric]
R102  1 kOhm 1%  [R_0402_1005Metric]
TP_EOL  TEST_PADS
TP_MCU_SWD  TEST_PADS
U25  2 channel 0.7 pF USB ESD

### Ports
1V8_MIC, 3V3_DIGITAL, 3V8_MODEM, BOOT0, FAULT, GND_DIGITAL, I2C2_SCL_BUS, I2C2_SDA_BUS, NRST, PWR_GOOD, REV_STRAP0, REV_STRAP1, SWCLK, SWDIO, TEST_UART_RX_U1, TEST_UART_TX_U1, USB_DM_U1, USB_DP_U1, USB_VBUS_SENSE

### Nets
1V8_MIC: TP_EOL.4(VSENSE_1V8) ; port 1V8_MIC
3V3_DIGITAL: TP_EOL.2(VTREF_3V3) TP_MCU_SWD.1(VTREF) ; port 3V3_DIGITAL
3V8_MODEM: TP_EOL.3(VSENSE_3V8) ; port 3V8_MODEM
BOOT0: TP_EOL.9(BOOT0) ; port BOOT0
FAULT: TP_EOL.8(FAULT) ; port FAULT
GND_DIGITAL: C77.2 D6.2 D7.2 D8.2 J11.A1(GND) J11.A12(GND) J11.B1(GND) J11.B12(GND) R93.2 R94.2 R96.2 R97.2 R98.2 TP_EOL.1(GND) TP_MCU_SWD.5(GND) U25.3 ; port GND_DIGITAL
I2C2_SCL_BUS: TP_EOL.12(I2C_SCL) ; port I2C2_SCL_BUS
I2C2_SDA_BUS: TP_EOL.13(I2C_SDA) ; port I2C2_SDA_BUS
NRST: TP_MCU_SWD.4(NRST) ; port NRST
PWR_GOOD: TP_EOL.7(PWR_GOOD) ; port PWR_GOOD
REV_STRAP0: TP_EOL.10(REV0) ; port REV_STRAP0
REV_STRAP1: TP_EOL.11(REV1) ; port REV_STRAP1
SWCLK: TP_MCU_SWD.3(SWCLK) ; port SWCLK
SWDIO: TP_MCU_SWD.2(SWDIO) ; port SWDIO
TEST_UART_RX_TP: R102.1 TP_EOL.6(DUT_RX)
TEST_UART_RX_U1: R102.2 ; port TEST_UART_RX_U1
TEST_UART_TX_TP: R101.2 TP_EOL.5(DUT_TX)
TEST_UART_TX_U1: R101.1 ; port TEST_UART_TX_U1
USB_CC1: D7.1 J11.A5(CC1) R93.1
USB_CC2: D8.1 J11.B5(CC2) R94.1
USB_DM_CONN: J11.A7(D-) J11.B7(D-) R92.2 U25.2
USB_DM_U1: R92.1 ; port USB_DM_U1
USB_DP_CONN: J11.A6(D+) J11.B6(D+) R91.2 U25.1
USB_DP_U1: R91.1 ; port USB_DP_U1
USB_SHIELD: C77.1 J11.SHIELD(SHELL) R97.1 R98.1
USB_VBUS_CONN: D6.1 J11.A4(VBUS) J11.A9(VBUS) J11.B4(VBUS) J11.B9(VBUS) R95.1
USB_VBUS_SENSE: R95.2 R96.1 ; port USB_VBUS_SENSE

Not connected (* = marked no-connect by the designer): J11 A8(SBU1)* B8(SBU2)*

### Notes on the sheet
- Every connected symbol pin has one explicit wire stub. Only hierarchical labels cross functional-sheet boundaries.

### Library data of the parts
C77 = C77_GRM155R72A472KA01D: Manufacturer: Murata; Population: FITTED; Authority: PROJECT_EMC_BASELINE
D6 = D6_TPD1E05U06DYAR: Manufacturer: Texas Instruments; Population: FITTED; Authority: TI_TPDxE05U06_RevO
D7 = D7_TPD1E05U06DYAR: Manufacturer: Texas Instruments; Population: FITTED; Authority: TI_TPDxE05U06_RevO
D8 = D8_TPD1E05U06DYAR: Manufacturer: Texas Instruments; Population: FITTED; Authority: TI_TPDxE05U06_RevO
J11 = J11_USB4105-GF-A-120: Manufacturer: CONTROLLED_AUTHORITY; Population: FITTED; Authority: PCB_MAIN_CONNECTOR_FIXTURE_PIN_AUTHORITY_REV_A.csv
R91 = R91_ERJ-2RKF22R0X: Manufacturer: Panasonic; Population: FITTED; Authority: ST_STM32U585_DS13086_Rev10
R92 = R92_ERJ-2RKF22R0X: Manufacturer: Panasonic; Population: FITTED; Authority: ST_STM32U585_DS13086_Rev10
R93 = R93_ERJ-2RKF5101X: Manufacturer: Panasonic; Population: FITTED; Authority: USB_Type-C_Release_2.5
R94 = R94_ERJ-2RKF5101X: Manufacturer: Panasonic; Population: FITTED; Authority: USB_Type-C_Release_2.5
R95 = R95_ERJ-2RKF1001X: Manufacturer: Panasonic; Population: FITTED; Authority: ST_STM32U585_DS13086_Rev10
R96 = R96_ERJ-2RKF1003X: Manufacturer: Panasonic; Population: FITTED; Authority: PROJECT_MAIN_AUTH_010
R97 = R97_ERJ-2RKF1004X: Manufacturer: Panasonic; Population: FITTED; Authority: PROJECT_EMC_BASELINE
R98 = R98_ERJ-2GE0R00X: Manufacturer: Panasonic; Population: DNP; Authority: PROJECT_EMC_BASELINE
R101 = R101_ERJ-2RKF22R0X: Manufacturer: Panasonic; Population: FITTED; Authority: PROJECT_EOL_DFT
R102 = R102_ERJ-2RKF1001X: Manufacturer: Panasonic; Population: FITTED; Authority: PROJECT_EOL_DFT
TP_EOL = TP_EOL_TEST_PADS: Manufacturer: CONTROLLED_AUTHORITY; Population: FITTED; Authority: PCB_MAIN_CONNECTOR_FIXTURE_PIN_AUTHORITY_REV_A.csv
TP_MCU_SWD = TP_MCU_SWD_TEST_PADS: Manufacturer: CONTROLLED_AUTHORITY; Population: FITTED; Authority: PCB_MAIN_CONNECTOR_FIXTURE_PIN_AUTHORITY_REV_A.csv
U25 = U25_TPD2EUSB30DRTR: Manufacturer: Texas Instruments; Population: FITTED; Authority: TI_TPD2EUSB30_datasheet

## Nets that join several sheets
1V8_MIC: PCB-MAIN_01_POWER (C20.1 J_PWR.5), PCB-MAIN_03_AUDIO (12 pins), PCB-MAIN_09_CONNECTORS_TEST (TP_EOL.4)
3V3_DIGITAL: PCB-MAIN_01_POWER (C19.1 J_PWR.3), PCB-MAIN_02_MCU (25 pins), PCB-MAIN_03_AUDIO (6 pins), PCB-MAIN_04_GNSS (5 pins), PCB-MAIN_05_CELLULAR (12 pins), PCB-MAIN_06_LORA (5 pins), PCB-MAIN_07_BLE (9 pins), PCB-MAIN_08_STORAGE_SENSORS (27 pins), PCB-MAIN_09_CONNECTORS_TEST (TP_EOL.2 TP_MCU_SWD.1)
3V8_MODEM: PCB-MAIN_01_POWER (J_PWR.1), PCB-MAIN_05_CELLULAR (FB1.1 R42.1), PCB-MAIN_09_CONNECTORS_TEST (TP_EOL.3)
AAD_CFG: PCB-MAIN_02_MCU (U1.77), PCB-MAIN_03_AUDIO (U7.16)
ACCEL_INT: PCB-MAIN_02_MCU (U1.63), PCB-MAIN_08_STORAGE_SENSORS (U3.12)
BLE_DFU_REQ: PCB-MAIN_02_MCU (U1.34), PCB-MAIN_07_BLE (R76.2 U11.39)
BLE_EN: PCB-MAIN_02_MCU (U1.5), PCB-MAIN_07_BLE (R77.1 U6.2)
BLE_RX_U1: PCB-MAIN_02_MCU (U1.45), PCB-MAIN_07_BLE (R74.2)
BLE_TX_U1: PCB-MAIN_02_MCU (U1.44), PCB-MAIN_07_BLE (R75.1)
BOOT0: PCB-MAIN_02_MCU (R2.1 U1.94), PCB-MAIN_09_CONNECTORS_TEST (TP_EOL.9)
CELL_DTR_U16: PCB-MAIN_02_MCU (U1.61), PCB-MAIN_05_CELLULAR (R29.1 U16.16)
CELL_PWRKEY_CMD: PCB-MAIN_02_MCU (U1.58), PCB-MAIN_05_CELLULAR (R24.1)
CELL_RESET_N_CMD: PCB-MAIN_02_MCU (U1.59), PCB-MAIN_05_CELLULAR (R26.1)
CELL_RI_U16: PCB-MAIN_02_MCU (U1.62), PCB-MAIN_05_CELLULAR (R33.2 U16.19)
CELL_RX_U16: PCB-MAIN_02_MCU (U1.93), PCB-MAIN_05_CELLULAR (R32.2 U16.21)
CELL_STATUS_U16: PCB-MAIN_02_MCU (U1.60), PCB-MAIN_05_CELLULAR (R34.1 U16.20)
CELL_TX_U16: PCB-MAIN_02_MCU (U1.92), PCB-MAIN_05_CELLULAR (R28.2 U16.17)
EN_AUX: PCB-MAIN_01_POWER (J_PWR.10), PCB-MAIN_02_MCU (U1.86)
EN_MODEM: PCB-MAIN_01_POWER (J_PWR.9), PCB-MAIN_02_MCU (U1.85)
FAULT: PCB-MAIN_01_POWER (J_PWR.8 R103.1), PCB-MAIN_09_CONNECTORS_TEST (TP_EOL.8)
GND_DIGITAL: PCB-MAIN_01_POWER (C19.2 J_PWR.4), PCB-MAIN_02_MCU (30 pins), PCB-MAIN_03_AUDIO (13 pins), PCB-MAIN_04_GNSS (17 pins), PCB-MAIN_06_LORA (21 pins), PCB-MAIN_07_BLE (11 pins), PCB-MAIN_08_STORAGE_SENSORS (27 pins), PCB-MAIN_09_CONNECTORS_TEST (16 pins)
GND_MIC: PCB-MAIN_01_POWER (C20.2 J_PWR.6), PCB-MAIN_03_AUDIO (20 pins)
GND_MODEM: PCB-MAIN_01_POWER (J_PWR.2), PCB-MAIN_05_CELLULAR (92 pins)
GNSS_PPS_U1: PCB-MAIN_02_MCU (U1.22), PCB-MAIN_04_GNSS (R58.2)
GNSS_RX_U1: PCB-MAIN_02_MCU (U1.25), PCB-MAIN_04_GNSS (R56.2)
GNSS_TX_U1: PCB-MAIN_02_MCU (U1.24), PCB-MAIN_04_GNSS (R57.1)
I2C2_SCL_BUS: PCB-MAIN_01_POWER (J_PWR.11), PCB-MAIN_08_STORAGE_SENSORS (R13.2 R15.2 U3.1 U4.1), PCB-MAIN_09_CONNECTORS_TEST (TP_EOL.12)
I2C2_SCL_U1: PCB-MAIN_02_MCU (U1.52), PCB-MAIN_08_STORAGE_SENSORS (R15.1)
I2C2_SDA_BUS: PCB-MAIN_01_POWER (J_PWR.12), PCB-MAIN_08_STORAGE_SENSORS (R14.2 R16.2 U3.4 U4.6), PCB-MAIN_09_CONNECTORS_TEST (TP_EOL.13)
I2C2_SDA_U1: PCB-MAIN_02_MCU (U1.53), PCB-MAIN_08_STORAGE_SENSORS (R16.1)
LORA_BUSY: PCB-MAIN_02_MCU (U1.56), PCB-MAIN_06_LORA (R66.1 U10.14)
LORA_DIO1: PCB-MAIN_02_MCU (U1.17), PCB-MAIN_06_LORA (R65.1 U10.13)
LORA_MISO_U1: PCB-MAIN_02_MCU (U1.30), PCB-MAIN_06_LORA (R72.2)
LORA_MOSI_U1: PCB-MAIN_02_MCU (U1.31), PCB-MAIN_06_LORA (R71.1)
LORA_NSS_U1: PCB-MAIN_02_MCU (U1.28), PCB-MAIN_06_LORA (R69.1)
LORA_RESET_N: PCB-MAIN_02_MCU (U1.57), PCB-MAIN_06_LORA (C68.1 R67.2 U10.15)
LORA_RXEN: PCB-MAIN_02_MCU (U1.55), PCB-MAIN_06_LORA (R64.1 U10.6)
LORA_SCK_U1: PCB-MAIN_02_MCU (U1.29), PCB-MAIN_06_LORA (R70.1)
LORA_TXEN: PCB-MAIN_02_MCU (U1.54), PCB-MAIN_06_LORA (R63.1 U10.7)
MIC_WAKE: PCB-MAIN_02_MCU (U1.67), PCB-MAIN_03_AUDIO (R23.1 U18.4)
NOR_CLK_U1: PCB-MAIN_02_MCU (U1.38), PCB-MAIN_08_STORAGE_SENSORS (R8.1)
NOR_IO0_U1: PCB-MAIN_02_MCU (U1.40), PCB-MAIN_08_STORAGE_SENSORS (R9.1)
NOR_IO1_U1: PCB-MAIN_02_MCU (U1.41), PCB-MAIN_08_STORAGE_SENSORS (R10.1)
NOR_IO2_U1: PCB-MAIN_02_MCU (U1.42), PCB-MAIN_08_STORAGE_SENSORS (R11.1)
NOR_IO3_U1: PCB-MAIN_02_MCU (U1.43), PCB-MAIN_08_STORAGE_SENSORS (R12.1)
NOR_NCS_U2: PCB-MAIN_02_MCU (U1.39), PCB-MAIN_08_STORAGE_SENSORS (R7.2 U2.7)
NRST: PCB-MAIN_02_MCU (C18.1 R1.2 U1.14), PCB-MAIN_09_CONNECTORS_TEST (TP_MCU_SWD.4)
PDM_CLK: PCB-MAIN_02_MCU (U1.37), PCB-MAIN_03_AUDIO (U7.17)
PDM_DATA1: PCB-MAIN_02_MCU (U1.33), PCB-MAIN_03_AUDIO (U7.21)
PDM_DATA2: PCB-MAIN_02_MCU (U1.87), PCB-MAIN_03_AUDIO (U7.20)
PDM_DATA3: PCB-MAIN_02_MCU (U1.35), PCB-MAIN_03_AUDIO (U7.19)
PDM_DATA4: PCB-MAIN_02_MCU (U1.3), PCB-MAIN_03_AUDIO (U7.18)
PWR_FAULT: PCB-MAIN_01_POWER (R103.2), PCB-MAIN_02_MCU (U1.82)
PWR_GOOD: PCB-MAIN_01_POWER (J_PWR.7), PCB-MAIN_02_MCU (U1.81), PCB-MAIN_09_CONNECTORS_TEST (TP_EOL.7)
REV_STRAP0: PCB-MAIN_02_MCU (U1.95), PCB-MAIN_09_CONNECTORS_TEST (TP_EOL.10)
REV_STRAP1: PCB-MAIN_02_MCU (U1.96), PCB-MAIN_09_CONNECTORS_TEST (TP_EOL.11)
SD_CK_U1: PCB-MAIN_02_MCU (U1.80), PCB-MAIN_08_STORAGE_SENSORS (R79.1)
SD_CMD_U1: PCB-MAIN_02_MCU (U1.83), PCB-MAIN_08_STORAGE_SENSORS (R80.1)
SD_D0_U1: PCB-MAIN_02_MCU (U1.65), PCB-MAIN_08_STORAGE_SENSORS (R81.1)
SD_D1_U1: PCB-MAIN_02_MCU (U1.66), PCB-MAIN_08_STORAGE_SENSORS (R82.1)
SD_D2_U1: PCB-MAIN_02_MCU (U1.78), PCB-MAIN_08_STORAGE_SENSORS (R83.1)
SD_D3_U1: PCB-MAIN_02_MCU (U1.79), PCB-MAIN_08_STORAGE_SENSORS (R84.1)
SD_DET: PCB-MAIN_02_MCU (U1.7), PCB-MAIN_08_STORAGE_SENSORS (C76.1 J12.CD R90.2 U24.4)
SIM1_DET: PCB-MAIN_02_MCU (U1.2), PCB-MAIN_05_CELLULAR (C52.1 J6.7 R48.2 U14.6)
SIM2_DET: PCB-MAIN_02_MCU (U1.4), PCB-MAIN_05_CELLULAR (C53.1 J7.7 R49.2 U15.6)
SIM_MUX_EN: PCB-MAIN_02_MCU (U1.1), PCB-MAIN_05_CELLULAR (R46.1)
SIM_MUX_SEL: PCB-MAIN_02_MCU (U1.97), PCB-MAIN_05_CELLULAR (R45.1 U13.14 U13.24)
SWCLK: PCB-MAIN_02_MCU (U1.76), PCB-MAIN_09_CONNECTORS_TEST (TP_MCU_SWD.3)
SWDIO: PCB-MAIN_02_MCU (U1.72), PCB-MAIN_09_CONNECTORS_TEST (TP_MCU_SWD.2)
TAMPER_IN_U1: PCB-MAIN_02_MCU (U1.64), PCB-MAIN_08_STORAGE_SENSORS (C78.1 R100.2)
TEST_UART_RX_U1: PCB-MAIN_02_MCU (U1.15), PCB-MAIN_09_CONNECTORS_TEST (R102.2)
TEST_UART_TX_U1: PCB-MAIN_02_MCU (U1.16), PCB-MAIN_09_CONNECTORS_TEST (R101.1)
USB_DM_U1: PCB-MAIN_02_MCU (U1.70), PCB-MAIN_09_CONNECTORS_TEST (R92.1)
USB_DP_U1: PCB-MAIN_02_MCU (U1.71), PCB-MAIN_09_CONNECTORS_TEST (R91.1)
USB_VBUS_SENSE: PCB-MAIN_02_MCU (U1.68), PCB-MAIN_09_CONNECTORS_TEST (R95.2 R96.1)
